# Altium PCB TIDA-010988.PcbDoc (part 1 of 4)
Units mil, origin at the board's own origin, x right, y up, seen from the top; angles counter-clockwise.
Board outline 3937.01 x 2559.06 mil, 4 copper layers (Top Layer, GND1, GND2, Bottom Layer), stack 61.6 mil thick; 270 components, 141 nets, 796 pads, 474 vias.
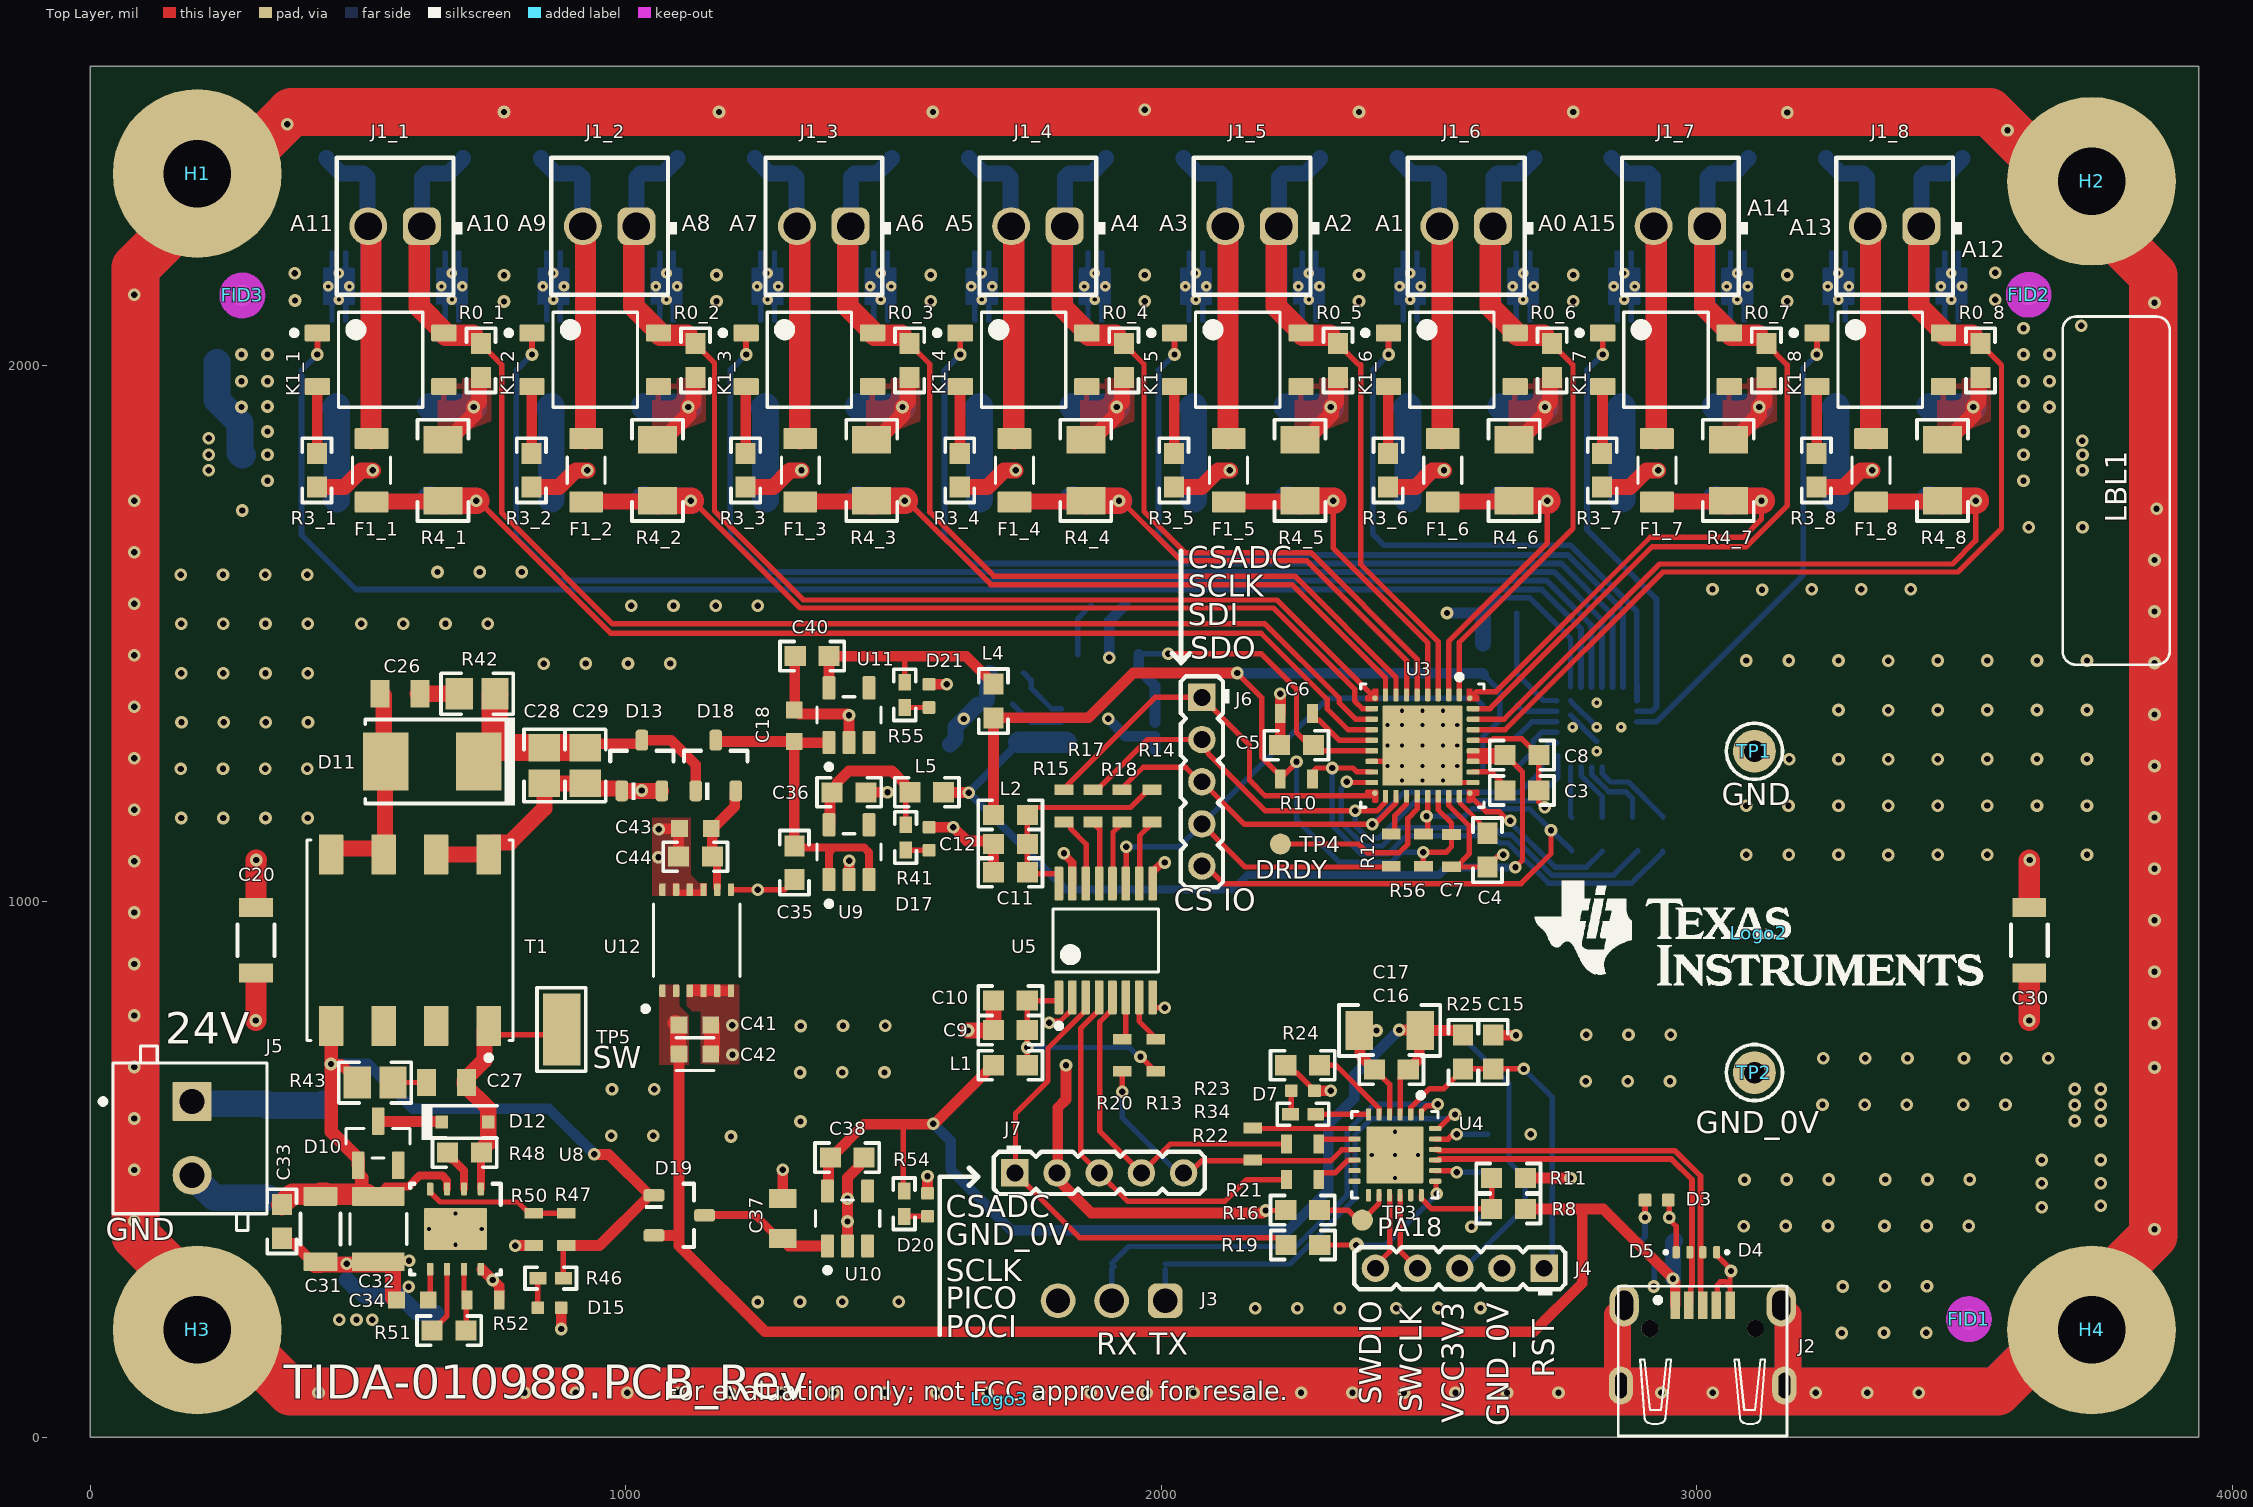
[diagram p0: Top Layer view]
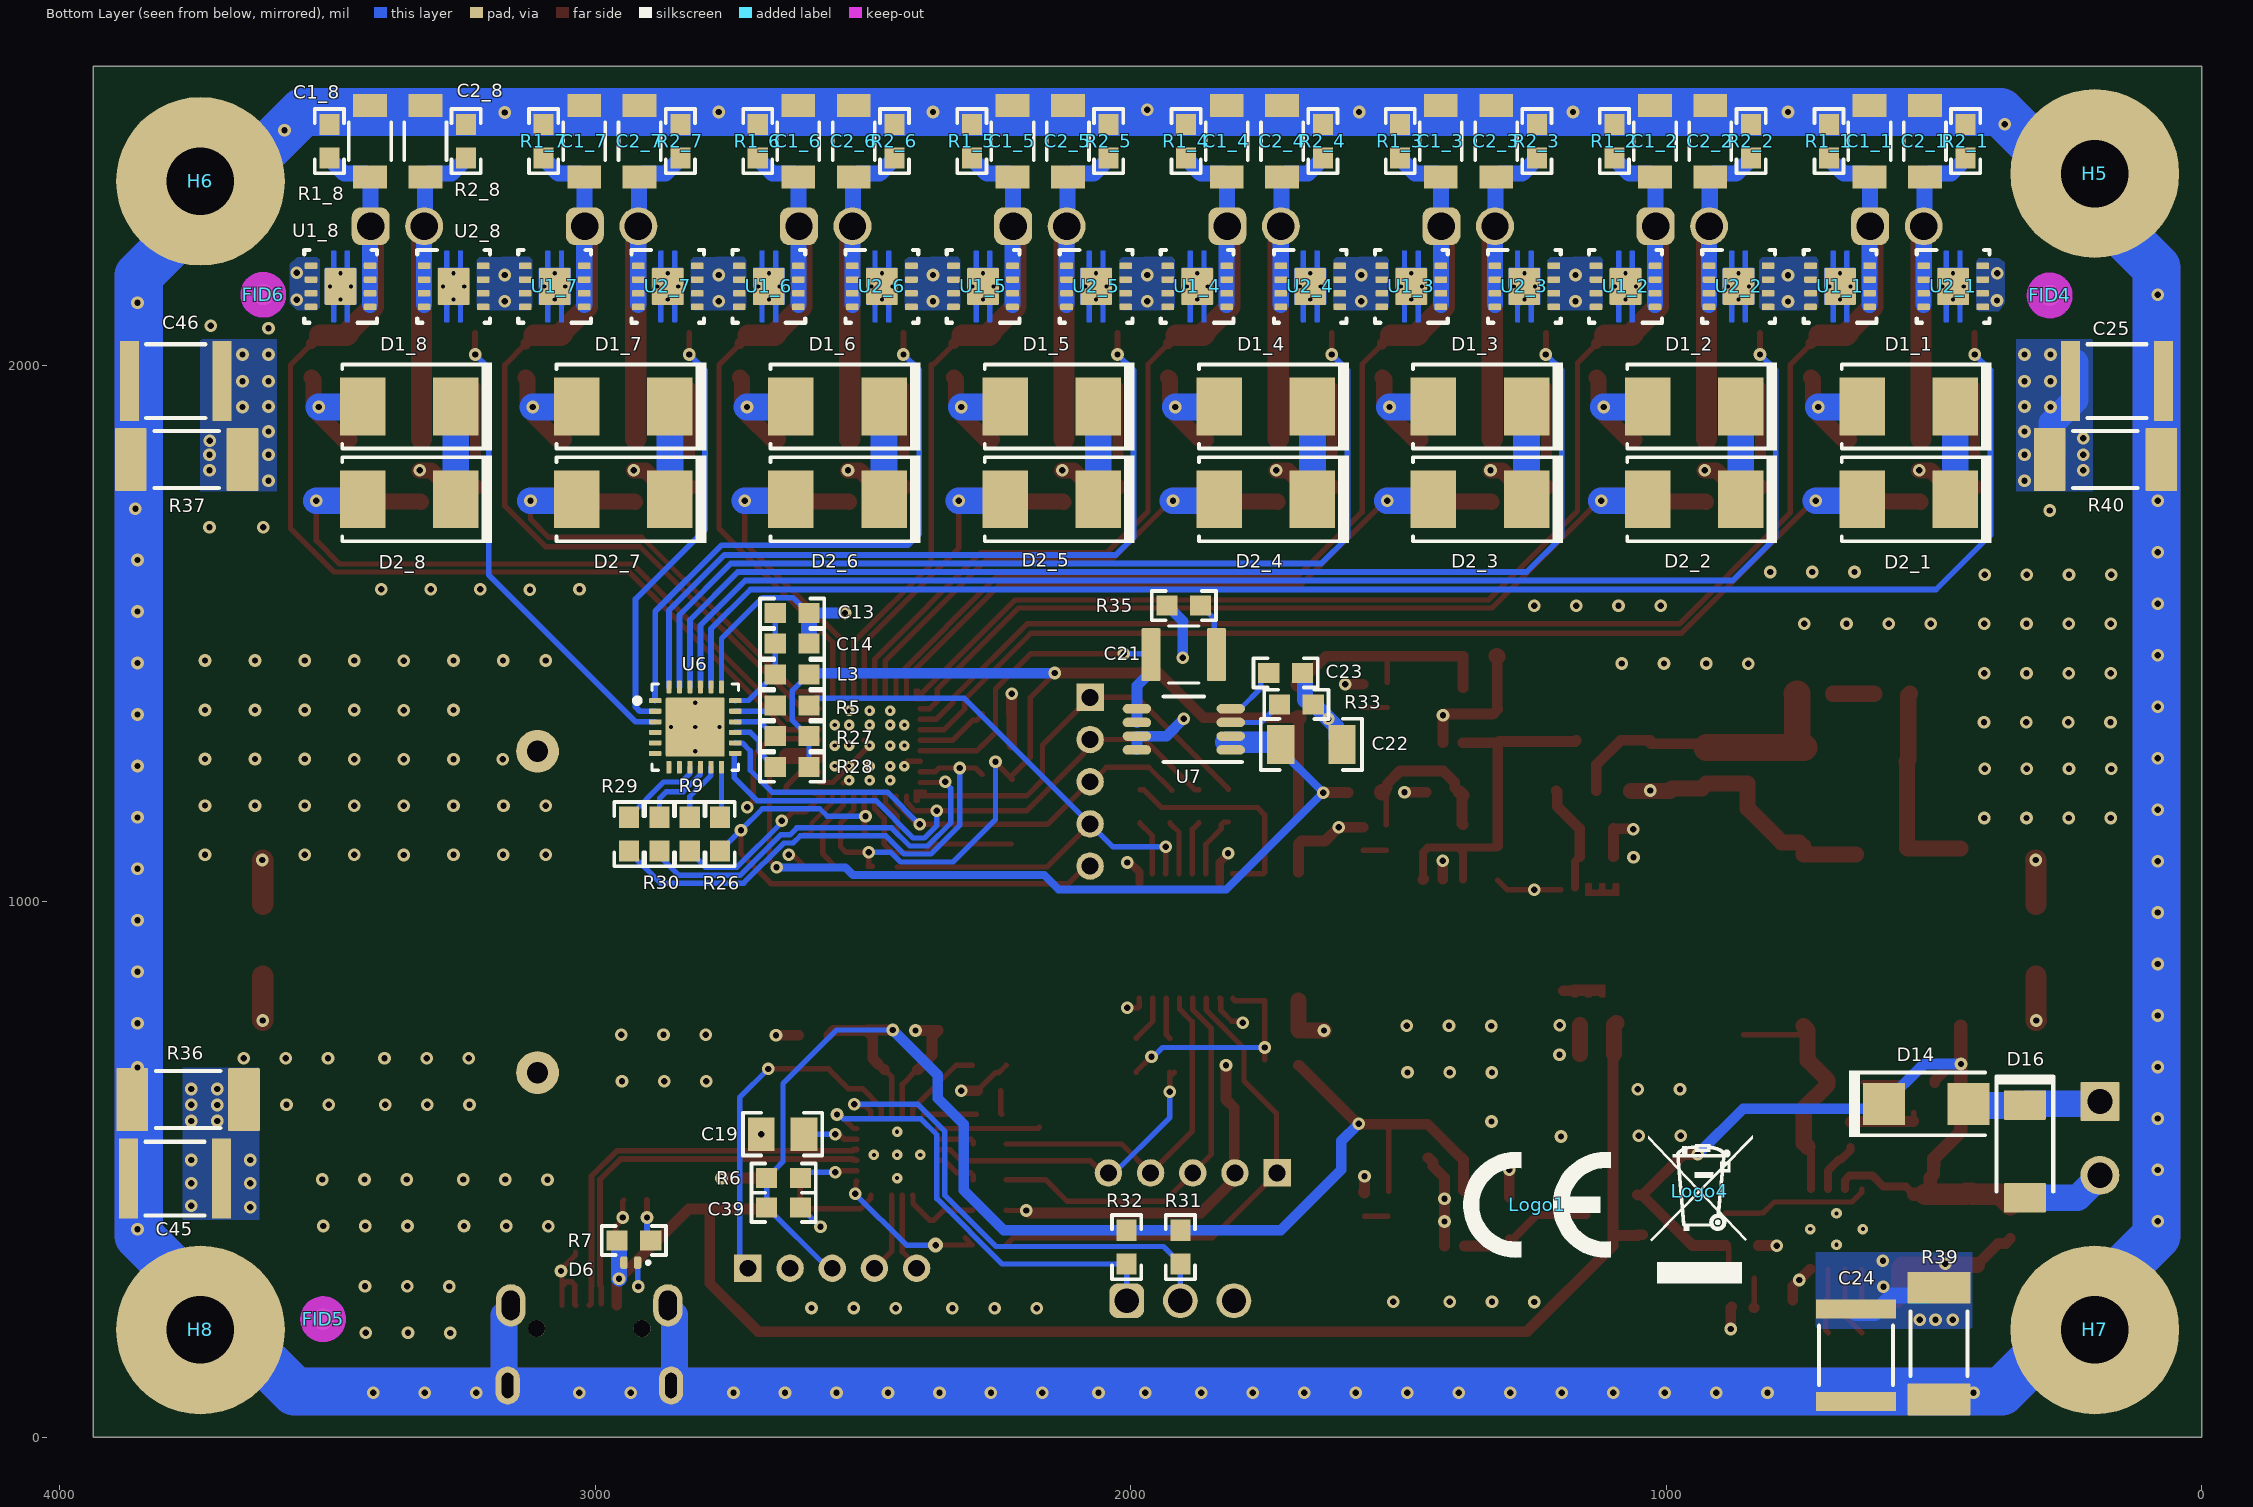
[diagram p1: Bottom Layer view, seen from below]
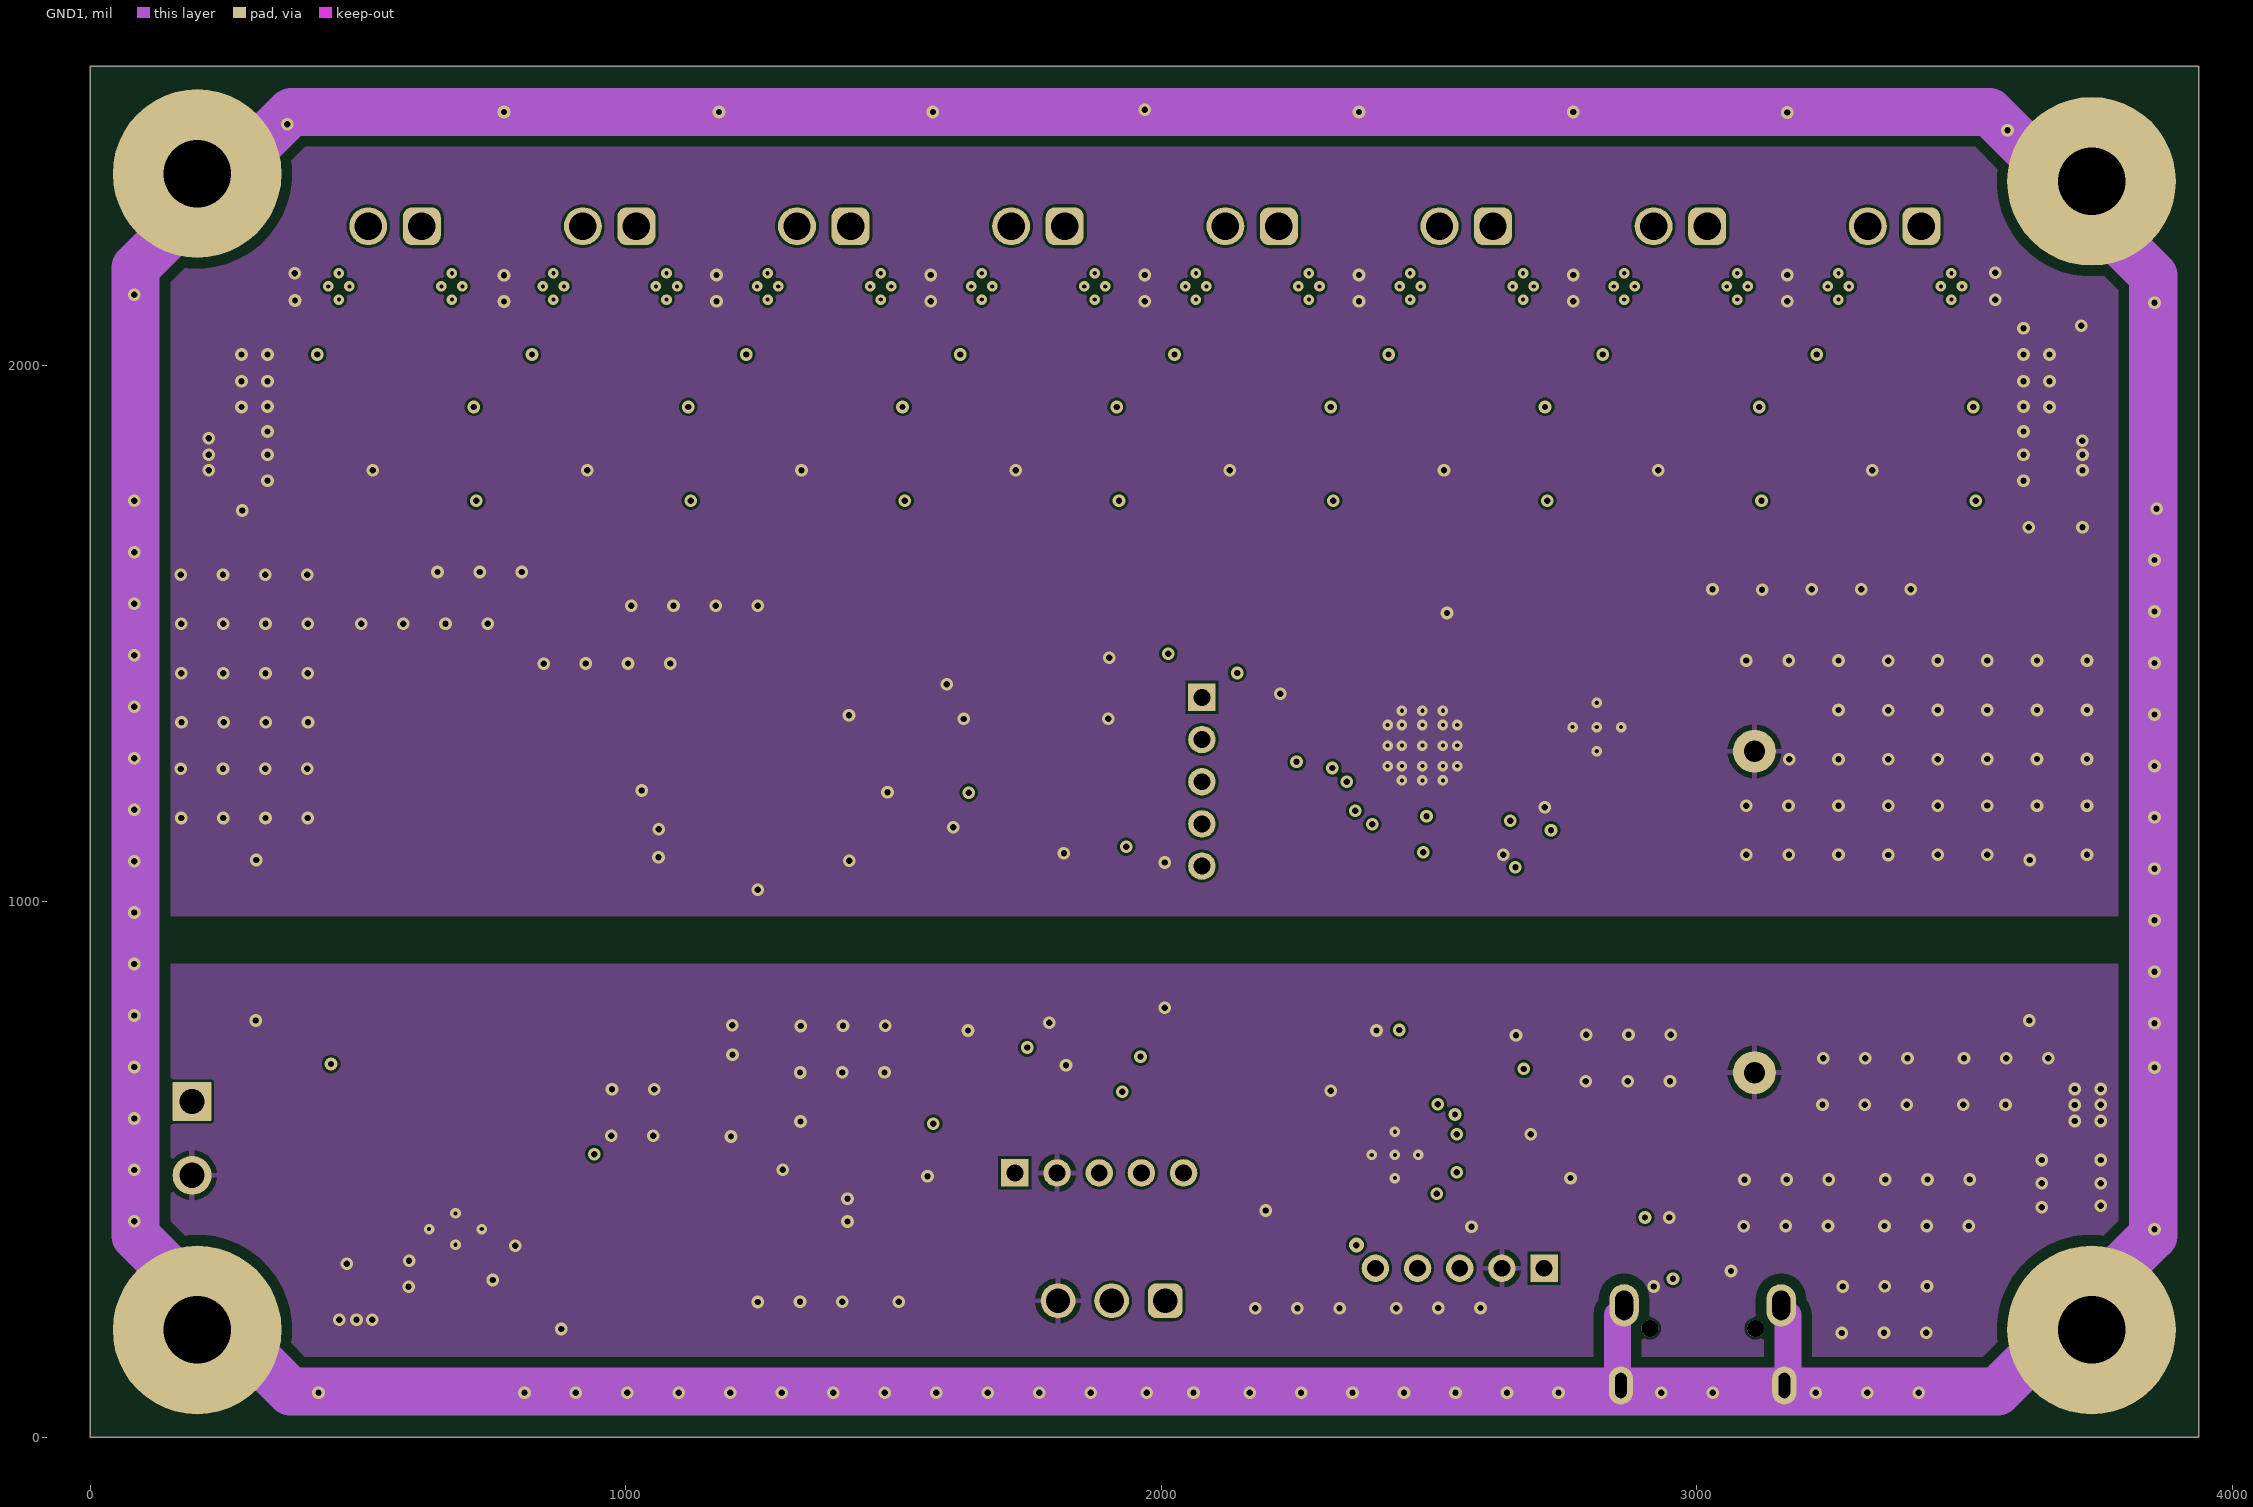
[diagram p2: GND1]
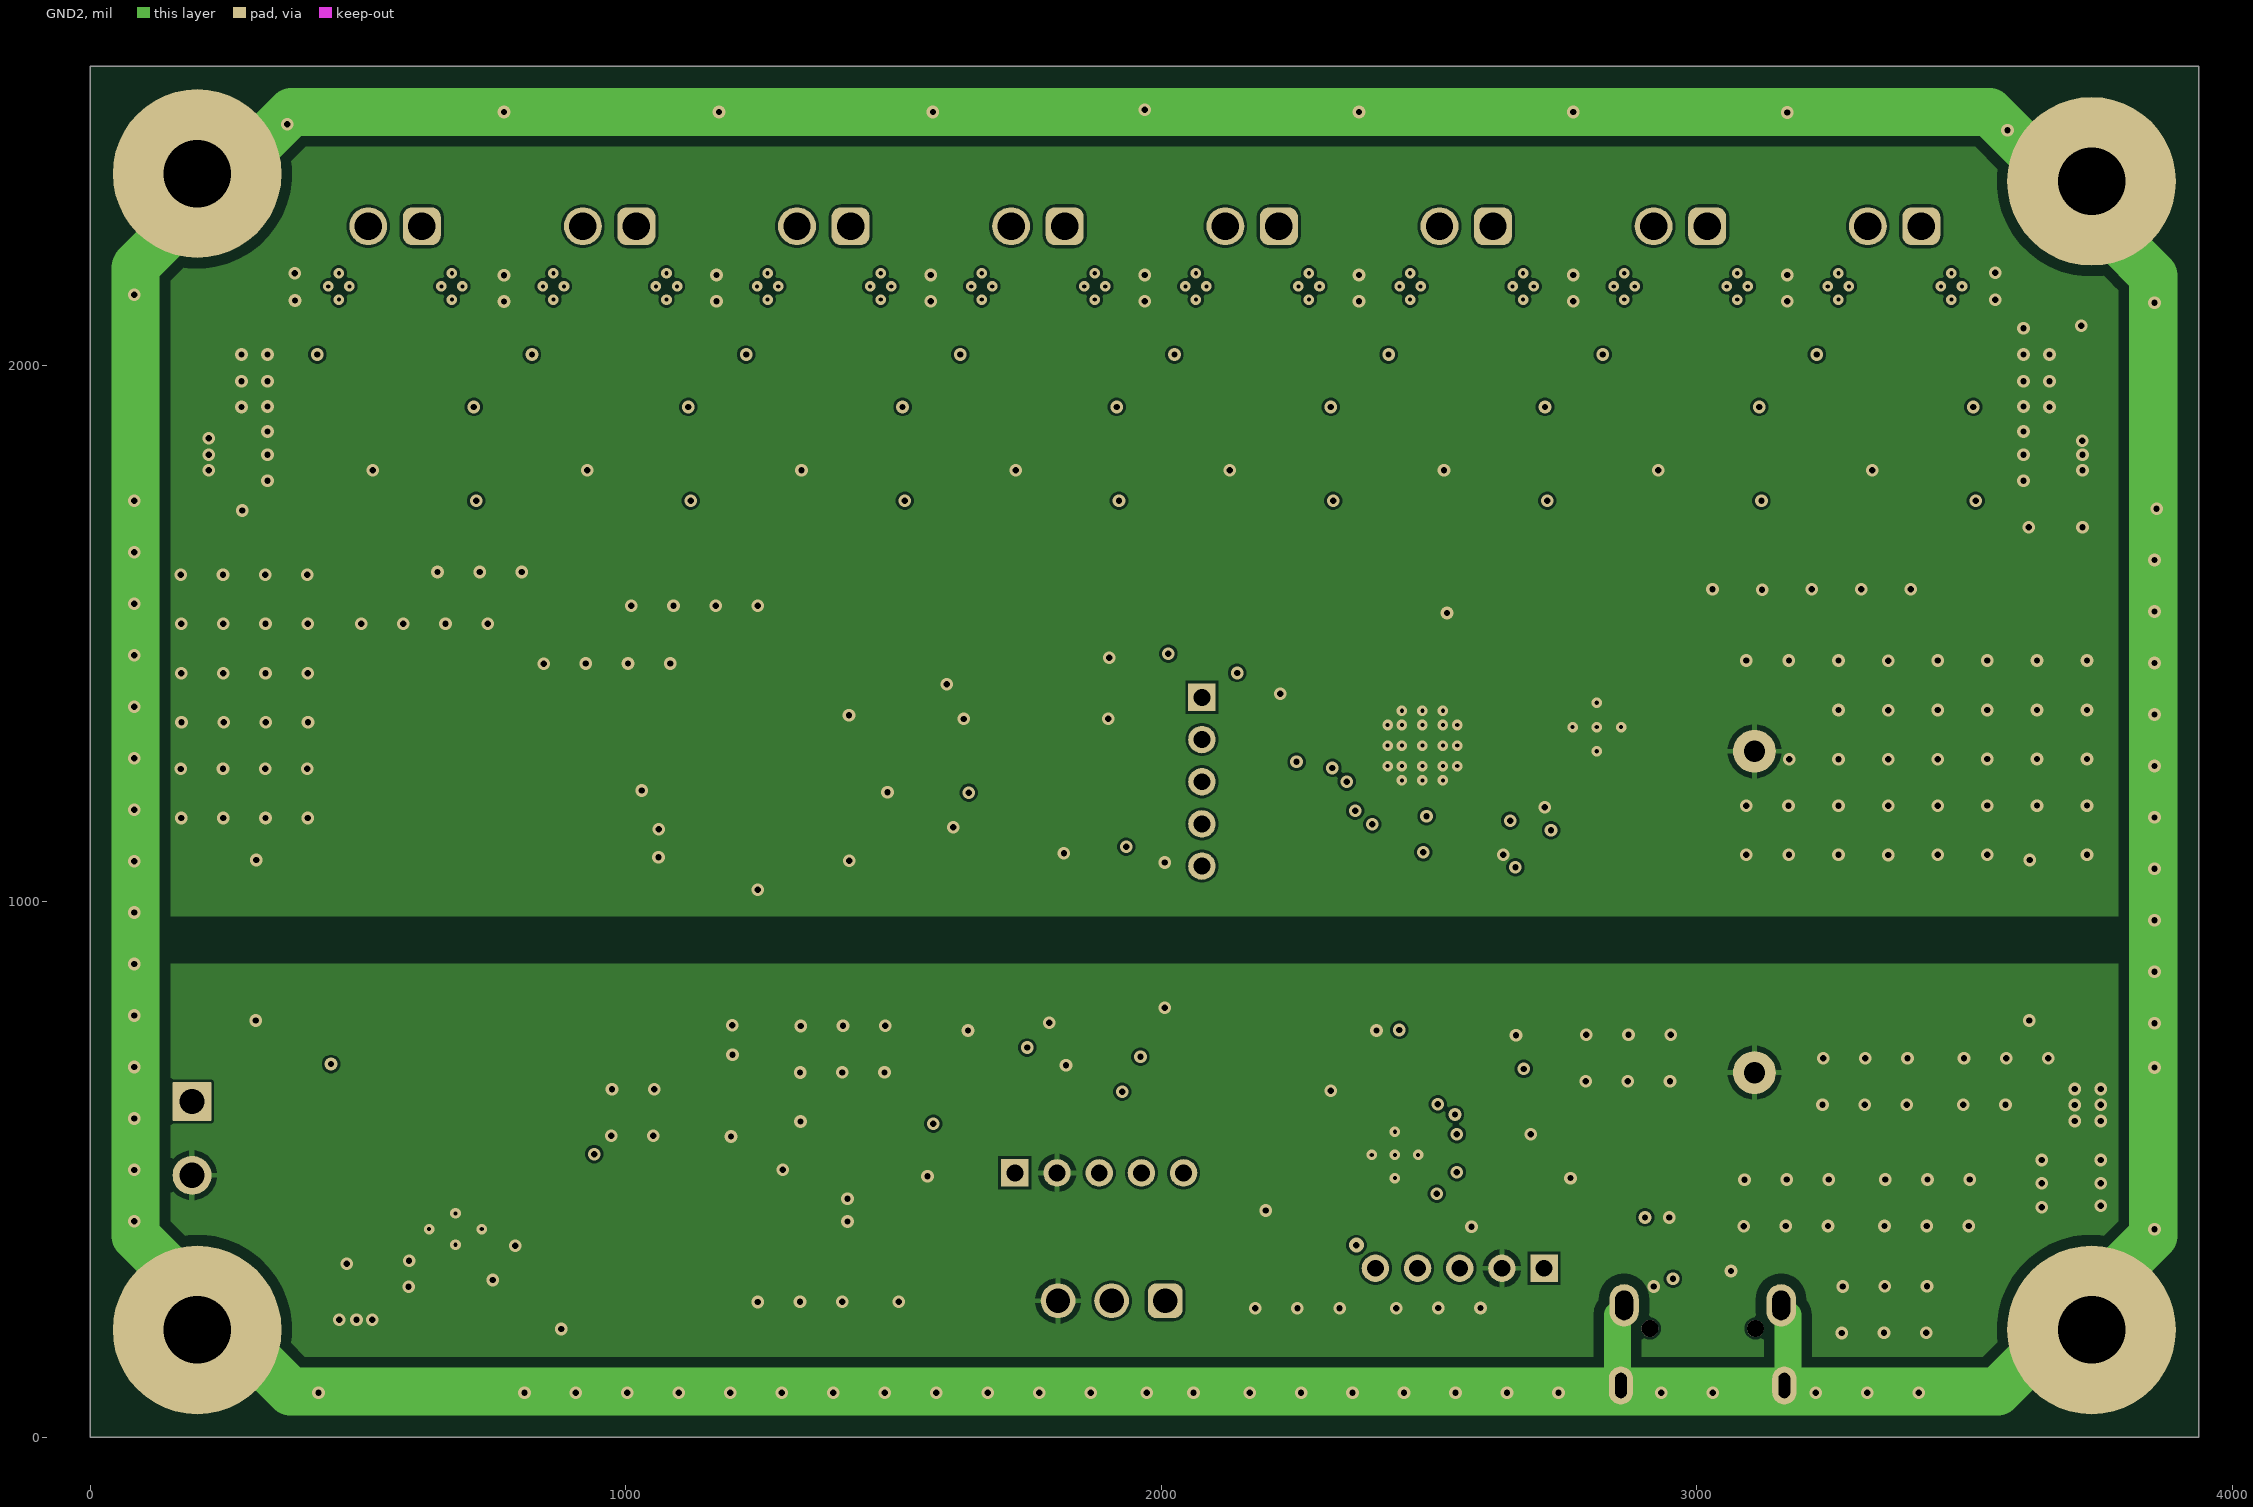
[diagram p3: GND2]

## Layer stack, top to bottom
Top Solder: solder mask 0.4, Solder Resist, Dk 3.5
Top Layer: signal copper 1.4
Dielectric 1: prepreg 9, PP-006, Dk 4.1
GND1: signal copper 1.4
Dielectric1: core 38, FR-4 High Tg, Dk 4.8
GND2: signal copper 1.4
Dielectric 2: prepreg 9, PP-006, Dk 4.1
Bottom Layer: signal copper 1.4
Bottom Solder: solder mask 0.4, Solder Resist, Dk 3.5

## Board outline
0,0 0,2559.06 3937.01,2559.06 3937.01,0

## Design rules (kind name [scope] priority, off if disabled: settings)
AcuteAngle [All] p1: minimum=4.50000000000000E+0001 checktracksonly=FALSE
AssemblyTestPointUsage [All] p1: valid=2
BoardOutlineClearance BoardOutlineClearance_MountingHoles [OnCopper and InComponentClass('Mounting Holes')] p1: gap=39.37 ignorepadtopadclearanceinfootprint=FALSE
BoardOutlineClearance BoardOutlineClearance_Poly [OnCopper and IsPoly] p2: gap=25 ignorepadtopadclearanceinfootprint=FALSE
BoardOutlineClearance [OnCopper and Not InComponentClass('Logo') and not InComponentClass('FiducialMark') and not InRegion(1000,500,4000,800) and not InPoly] p3: gap=40 ignorepadtopadclearanceinfootprint=FALSE
Clearance Clearance_EGND [InNet('E_GND')] p1: gap=20 ignorepadtopadclearanceinfootprint=TRUE
Clearance Clearance_Keepouts [((IsTrack Or IsArc) And Not InPoly) And IsFree and IsKeepOut vs ((IsTrack Or IsArc) And Not InPoly) And IsFree and IsKeepOut] p2: gap=0 ignorepadtopadclearanceinfootprint=FALSE
Clearance Clearance_Poly [InPolygon] p3: gap=5 ignorepadtopadclearanceinfootprint=TRUE
Clearance Clearance_FiducialMark [IsKeepOut and InComponentClass('FiducialMark') vs IsPad and InComponentClass('FiducialMark')] p4: gap=0 ignorepadtopadclearanceinfootprint=FALSE
Clearance [All] p5: gap=5 ignorepadtopadclearanceinfootprint=TRUE
ComponentClearance ComponentClearance_L3R29 [InComponent('R29') or InComponent('L3')] p1: gap=0 collisioncheckmode=3 verticalgap=0 showdistances=FALSE
ComponentClearance ComponentClearance_J2J3 [InComponent('J2') or InComponent('J3')] p2: gap=0 collisioncheckmode=3 verticalgap=0 showdistances=FALSE
ComponentClearance ComponentClearance_J4J5 [InComponent('J4') or InComponent('J5')] p3: gap=0 collisioncheckmode=3 verticalgap=0 showdistances=FALSE
ComponentClearance ComponentClearance_J11_J12 [InComponent('J11*') or InComponent('J12*')] p4: gap=0 collisioncheckmode=3 verticalgap=0 showdistances=FALSE
ComponentClearance ComponentClearance_MountingHoles_FiducialMarks [InComponentClass('Mounting Holes') vs InComponentClass('FiducialMark')] p5: gap=50 collisioncheckmode=3 verticalgap=10 showdistances=FALSE
ComponentClearance ComponentClearance_Shunt [InComponentClass('Header') vs InComponentClass('Shunt')] p6: gap=0 collisioncheckmode=3 verticalgap=0 showdistances=FALSE
ComponentClearance ComponentClearance_Logo [InComponentClass('Logo')] p7: gap=30 collisioncheckmode=3 verticalgap=10 showdistances=FALSE
ComponentClearance ComponentClearance_ScrewToNut [(HasFootprint('NY PMS 440 0025 PH')) vs (HasFootprint('Keystone_1902C'))] p8: gap=5 collisioncheckmode=3 verticalgap=10 showdistances=FALSE
ComponentClearance ComponentClearance_MountingHoles [InComponentClass('Mounting Holes')] p9: gap=78.74 collisioncheckmode=3 verticalgap=100000 showdistances=FALSE
ComponentClearance ComponentClearance_SmallPassives [HasFootprint('0201*') or HasFootprint('0402*') or HasFootprint('0508') or HasFootprint('0603*') or HasFootprint('0612') or HasFootprint('0805*') or HasFootprint('0815*') or HasFootprint('0830*') or HasFootprint('1206*') or HasFootprint('1210*') or HasFootprint('1808*') or HasFootprint('1812*') or HasFootprint('1825*') or HasFootprint('2010*') or HasFootprint('2220*') or HasFootprint('2225*') or HasFootprint('2512*') or HasFootprint('2728*') or HasFootprint('3518*') or HasFootprint('DPY0002A') vs HasFootprint('0201*') or HasFootprint('0402*') or HasFootprint('0508') or HasFootprint('0603*') or HasFootprint('0612') or HasFootprint('0805*') or HasFootprint('0815*') or HasFootprint('0830*') or HasFootprint('1206*') or HasFootprint('1210*') or HasFootprint('1808*') or HasFootprint('1812*') or HasFootprint('1825*') or HasFootprint('2010*') or HasFootprint('2220*') or HasFootprint('2225*') or HasFootprint('2512*') or HasFootprint('2728*') or HasFootprint('3518*') or HasFootprint('DPY0002A')] p10: gap=10 collisioncheckmode=3 verticalgap=10 showdistances=FALSE
ComponentClearance ComponentClearance_THtoSMT [IsThruComponent vs IsSMTComponent] p11: gap=20 collisioncheckmode=3 verticalgap=30 showdistances=FALSE
ComponentClearance ComponentClearance_THtoTH [IsThruComponent vs IsThruComponent] p12: gap=20 collisioncheckmode=3 verticalgap=30 showdistances=FALSE
ComponentClearance [All] p13: gap=10 collisioncheckmode=3 verticalgap=10 showdistances=FALSE
DiffPairsRouting DiffPairsRouting_1 [InDifferentialPairClass('D90')] p1: maxlimit=5 minlimit=5 mostfreqgap=5 toplayer_minwidth=10.82 toplayer_maxwidth=10.82 toplayer_prefwidth=10.82 midlayer1_minwidth=4.64 midlayer1_maxwidth=4.64 midlayer1_prefwidth=4.64 midlayer2_minwidth=4.64 midlayer2_maxwidth=4.64 midlayer2_prefwidth=4.64 bottomlayer_minwidth=10.82 bottomlayer_maxwidth=10.82 bottomlayer_prefwidth=10.82 impedanceprofiledriven=TRUE maxuncoupledlength=500
DiffPairsRouting [All] p2: maxlimit=100 minlimit=10 mostfreqgap=10 toplayer_minwidth=15 toplayer_maxwidth=15 toplayer_prefwidth=15 midlayer1_minwidth=15 midlayer1_maxwidth=15 midlayer1_prefwidth=15 midlayer2_minwidth=15 midlayer2_maxwidth=15 midlayer2_prefwidth=15 bottomlayer_minwidth=15 bottomlayer_maxwidth=15 bottomlayer_prefwidth=15 maxuncoupledlength=1000
FabricationTestPointUsage TestPointUsage [All] p1: valid=2 allowmultiple=FALSE
FabricationTestpoint Testpoint [All] p1: side=3 testpointundercomponent=TRUE minsize=40 maxsize=100 preferedsize=60 minholesize=0 maxholesize=40 preferedholesize=32 testpointgrid=1 allowsidetop=TRUE allowsidebottom=TRUE usegrid=TRUE gridtolerance=0.01
FanoutControl Fanout_LCC [IsLCC] p1: bgadir=Out bgaviamode=Centered fanoutstyle=Auto fanoutdirection=Alternating viagrid=1 // Fanout_LCC (Default Rule)
FanoutControl Fanout_BGA [IsBGA] p2: bgadir=Out bgaviamode=Centered fanoutstyle=Auto fanoutdirection=Alternating viagrid=1 // Fanout_BGA (Default Rule)
FanoutControl Fanout_Default [All] p4: bgadir=Out bgaviamode=Centered fanoutstyle=Auto fanoutdirection=Alternating viagrid=1 // Fanout_Default (Default Rule)
FanoutControl Fanout_Small [(CompPinCount < 5)] p5: bgadir=Out bgaviamode=Centered fanoutstyle=Auto fanoutdirection=OutThenIn viagrid=1 // Fanout_Small (Default Rule)
HoleSize [All] p1: absolutevalues=TRUE maxlimit=251 minlimit=7.87 maxpercent=80.000 minpercent=20.000
MinimumAnnularRing MinimumAnnularRing_ThermalPadVias [IsVia and InAnyComponent] p1: minimumring=5.91
MinimumAnnularRing [All] p2: minimumring=5.91
MinimumSolderMaskSliver MinimumSolderMaskSliver_Logo [InComponentClass('Logo') vs InComponentClass('Logo')] p1: minsoldermaskwidth=0.7
MinimumSolderMaskSliver [All] p2: minsoldermaskwidth=3.94
PlaneClearance PlaneClearance_1 [InNet('E_GND')] p1: clearance=100
PlaneClearance [All] p2: clearance=20
PlaneConnect [All] p1: planeconnectstyle=Relief reliefexpansion=10 reliefentries=4 reliefconductorwidth=10 reliefairgap=10
PolygonConnect PolygonConnect_SMD [HasFootprint('0201*') or HasFootprint('*0402*') or HasFootprint('0508') or HasFootprint('0603*') or HasFootprint('0612') or HasFootprint('0805*') or HasFootprint('0815*') or HasFootprint('0830*') or HasFootprint('*1206*') or HasFootprint('*1210*') or HasFootprint('1808*') or HasFootprint('1812*') or HasFootprint('1825*') or HasFootprint('2010*') or HasFootprint('2220*') or HasFootprint('2225*') or HasFootprint('2512*') or HasFootprint('2728*') or HasFootprint('3518*') or HasFootprint('DPY0002A') or IsVia or HasFootprint('DBV*') or HasFootprint('WE-LQS*') or HasFootprint('SM_RADIAL_C') or HasFootprint('DRB*') or HasFootprint('691382010004') or HasFootprint('691382010002') or HasFootprint('*SOD128*') or HasFootprint('WE-SLM') or HasFootprint('WCAP*') or HasFootprint('RAQ0012B-MFG')or HasFootprint('FP-CHV2010-FX-3304ELF_2010-MFG')] p1: connectstyle=Direct reliefconductorwidth=10 reliefentries=4 polygonreliefangle="90 Angle" airgapwidth=10
PolygonConnect [All] p2: connectstyle=Relief reliefconductorwidth=10 reliefentries=4 polygonreliefangle="90 Angle" airgapwidth=10
RoomDefinition IN1 [InComponentClass('IN1')] p1: confinementstyle=ConfineIn formatcopy=TRUE lockcomponents=FALSE outline 362.31,2512.47 362.31,1643.16 779.44,1643.16 779.44,2512.47
RoomDefinition IN3 [InComponentClass('IN3')] p2: confinementstyle=ConfineIn formatcopy=TRUE lockcomponents=TRUE outline 1162.79,2512.47 1162.79,1643.16 1579.92,1643.16 1579.92,2512.47
RoomDefinition IN2 [InComponentClass('IN2')] p3: confinementstyle=ConfineIn formatcopy=TRUE lockcomponents=FALSE outline 762.93,2512.47 762.93,1643.16 1180.06,1643.16 1180.06,2512.47
RoomDefinition IN5 [InComponentClass('IN5')] p4: confinementstyle=ConfineIn formatcopy=TRUE lockcomponents=FALSE outline 1962.51,2512.47 1962.51,1643.16 2379.64,1643.16 2379.64,2512.47
RoomDefinition IN4 [InComponentClass('IN4')] p5: confinementstyle=ConfineIn formatcopy=TRUE lockcomponents=FALSE outline 1562.65,2512.47 1562.65,1643.16 1979.78,1643.16 1979.78,2512.47
RoomDefinition IN6 [InComponentClass('IN6')] p6: confinementstyle=ConfineIn formatcopy=TRUE lockcomponents=FALSE outline 2362.37,2512.47 2362.37,1643.16 2779.5,1643.16 2779.5,2512.47
RoomDefinition IN7 [InComponentClass('IN7')] p7: confinementstyle=ConfineIn formatcopy=TRUE lockcomponents=FALSE outline 2762.24,2512.47 2762.24,1643.16 3179.36,1643.16 3179.36,2512.47
RoomDefinition IN8 [InComponentClass('IN8')] p8: confinementstyle=ConfineIn formatcopy=TRUE lockcomponents=FALSE outline 3162.1,2512.47 3162.1,1643.16 3579.23,1643.16 3579.23,2512.47
RoutingVias [All] p1: holewidth=11.81 width=23.62 viastyle="Through Hole" minholewidth=5.91 minwidth=18 maxholewidth=40 maxwidth=65
RoutingVias ThermalPadVias [IsVia and InAnyComponent] p2: holewidth=5 width=19.68 viastyle="Through Hole" minholewidth=5 minwidth=19.68 maxholewidth=12.99 maxwidth=23.62
SilkToBoardRegionClearance [Not ((IsComment or IsDesignator) And (Hide <> 'False')) and not InRegion(1000,500,4000,800)] p1:
SilkToSilkClearance SilkToSilkClearance_Pb-FreeLogo [(HasFootprint('Pb-Free_Overlay_Medium') OR HasFootprint('Pb-Free_Overlay_Small')) vs (HasFootprint('Pb-Free_Overlay_Medium') OR HasFootprint('Pb-Free_Overlay_Small'))] p1: silktosilkclearance=0
SilkToSilkClearance [All] p2: silktosilkclearance=3.94
SilkToSolderMaskClearance SilkToComponentPadClearance [(IsPad or IsFill or IsRegion) and InAnycomponent] p1: minsilkscreentomaskgap=5 clearancetoexposedcopper=TRUE
SilkToSolderMaskClearance "Silk to Solder Mask Opening" [All] p2: minsilkscreentomaskgap=3.94 clearancetoexposedcopper=FALSE
SolderMaskExpansion [All] p1: expansion=1.97 istentingtop=FALSE
UnRoutedNet [All] p1: checkbadconnections=TRUE
Width [All] p1: maxlimit=100 minlimit=6 preferedwidth=10 checkconnectedcopper=TRUE
13 further rules are at their usual default settings.

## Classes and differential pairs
component class Header: J3 J4 J6 J7
component class IN6: C1_6 C2_6 D1_6 D2_6 F1_6 J1_6 K1_6 R0_6 R1_6 R2_6 R3_6 R4_6 U1_6 U2_6
component class IN5: C1_5 C2_5 D1_5 D2_5 F1_5 J1_5 K1_5 R0_5 R1_5 R2_5 R3_5 R4_5 U1_5 U2_5
component class IN2: C1_2 C2_2 D1_2 D2_2 F1_2 J1_2 K1_2 R0_2 R1_2 R2_2 R3_2 R4_2 U1_2 U2_2
component class IN1: C1_1 C2_1 D1_1 D2_1 F1_1 J1_1 K1_1 R0_1 R1_1 R2_1 R3_1 R4_1 U1_1 U2_1
differential pair class D90: USB_D
channel class TIDA-010988_Input: IN1 IN2 IN3 IN4 IN5 IN6 IN7 IN8
component class U_TIDA-010988_Power: C18 C24 C25 C26 C27 C28 C29 C31 C32 C33 C34 C35 C36 C37 C38 C40 C41 C42 C43 C44 C45 C46 D10 D11 D12 D13 D14 D15 D16 D17 D18 D19 D20 D21 J5 R36 R37 R39 R40 R41 R42 R43 R46 R47 R48 R50 R51 R52 R54 R55 T1 TP5 U8 U9 U10 U11 U12
component class IN8: C1_8 C2_8 D1_8 D2_8 F1_8 J1_8 K1_8 R0_8 R1_8 R2_8 R3_8 R4_8 U1_8 U2_8
component class IN7: C1_7 C2_7 D1_7 D2_7 F1_7 J1_7 K1_7 R0_7 R1_7 R2_7 R3_7 R4_7 U1_7 U2_7
component class IN4: C1_4 C2_4 D1_4 D2_4 F1_4 J1_4 K1_4 R0_4 R1_4 R2_4 R3_4 R4_4 U1_4 U2_4
component class IN3: C1_3 C2_3 D1_3 D2_3 F1_3 J1_3 K1_3 R0_3 R1_3 R2_3 R3_3 R4_3 U1_3 U2_3
component class U_TIDA-010988_ADC+MCU: C3 C4 C5 C6 C7 C8 C9 C10 C11 C12 C13 C14 C15 C16 C17 C19 C20 C21 C22 C23 C30 C39 D3 D4 D5 D6 D7 J2 J3 J4 J6 J7 L1 L2 L3 L4 L5 R5 R6 R7 R8 R9 R10 R11 R12 R13 R14 R15 R16 R17 R18 R19 R20 R21 R22 R23 R24 R25 R26 R27 R28 R29 R30 R31 R32 R33 R34 R35 R56 TP1 TP2 TP3 TP4 U3 U4 U5 U6 U7
component class "Mounting Holes": H1 H2 H3 H4
component class Logo: Logo2
component class U_TIDA-010988_Hardware: FID1 FID2 FID3 FID4 FID5 FID6 H1 H2 H3 H4 H5 H6 H7 H8 LBL1 Logo1 Logo2 Logo3 Logo4 ZZ1 ZZ2 ZZ3 ZZ4
component class FiducialMark: FID1 FID2 FID3 FID4 FID5 FID6
component class AssemblyNote: ZZ1 ZZ2 ZZ3 ZZ4
component class Label: LBL1
differential pair USB_D: +USB_D_P -USB_D_N

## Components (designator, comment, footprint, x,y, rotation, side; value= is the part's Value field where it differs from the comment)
C1_1 "C1206C223KDRACTU" 1206_190 620.59,2419.41 r90 bottom value=0.022uF (schematic designator C1)
C1_2 "C1206C223KDRACTU" 1206_190 1021.21,2419.41 r90 bottom value=0.022uF (schematic designator C1)
C1_3 "C1206C223KDRACTU" 1206_190 1421.07,2419.41 r90 bottom value=0.022uF (schematic designator C1)
C1_4 "C1206C223KDRACTU" 1206_190 1820.93,2419.41 r90 bottom value=0.022uF (schematic designator C1)
C1_5 "C1206C223KDRACTU" 1206_190 2220.8,2419.41 r90 bottom value=0.022uF (schematic designator C1)
C1_6 "C1206C223KDRACTU" 1206_190 2620.66,2419.41 r90 bottom value=0.022uF (schematic designator C1)
C1_7 "C1206C223KDRACTU" 1206_190 3020.52,2419.41 r90 bottom value=0.022uF (schematic designator C1)
C1_8 "C1206C223KDRACTU" 1206_190 3420.38,2419.41 r90 bottom value=0.022uF (schematic designator C1)
C2_1 "C1206C223KDRACTU" 1206_190 517.16,2419.41 r270 bottom value=0.022uF (schematic designator C2)
C2_2 "C1206C223KDRACTU" 1206_190 917.78,2419.41 r270 bottom value=0.022uF (schematic designator C2)
C2_3 "C1206C223KDRACTU" 1206_190 1317.64,2419.41 r270 bottom value=0.022uF (schematic designator C2)
C2_4 "C1206C223KDRACTU" 1206_190 1717.51,2419.41 r270 bottom value=0.022uF (schematic designator C2)
C2_5 "C1206C223KDRACTU" 1206_190 2117.37,2419.41 r270 bottom value=0.022uF (schematic designator C2)
C2_6 "C1206C223KDRACTU" 1206_190 2517.23,2419.41 r270 bottom value=0.022uF (schematic designator C2)
C2_7 "C1206C223KDRACTU" 1206_190 2917.09,2419.41 r270 bottom value=0.022uF (schematic designator C2)
C2_8 "C1206C223KDRACTU" 1206_190 3316.95,2419.41 r270 bottom value=0.022uF (schematic designator C2)
C3 "885012206076" 0603 2673.43,1207.13 r0 top value=1uF
C4 "885012206076" 0603 2609.12,1095.82 r270 top value=1uF
C5 "885012206076" 0603 2252.41,1291.67 r180 top value=1uF
C6 "885012206076" 0603S 2252.41,1350.91 r180 top value=1uF
C7 "885012206076" 0603S 2541.89,1094.99 r270 top value=1uF
C8 "885012206076" 0603 2673.49,1273.08 r0 top value=1uF
C9 "885012206071" 0603 1718.26,759.71 r180 top value=0.1uF
C10 "885012206071" 0603 1718.26,814.71 r180 top value=0.1uF
C11 "885012206071" 0603 1718.48,1054.5 r180 top value=0.1uF
C12 "885012206071" 0603 1718.48,1107.22 r180 top value=0.1uF
C13 "885012206071" 0603 2632.33,1538.44 r180 bottom value=0.1uF
C14 "885012206071" 0603 2632.33,1481.39 r180 bottom value=0.1uF
C15 "C0603H103J3GACTU" 0603 2619.89,718.78 r90 top value=0.01uF
C16 "885012206071" 0603 2429.63,685.94 r0 top value=0.1uF
C17 "885012208069" 1206 2426.47,758.98 r0 top value=10uF
C18 "885012206075" WCAP-CSGP_0603_L1.6W0.8H0.8_Reflow 1314.86,1328.04 r270 top
C19 "08053D474KAT2A" 0805_HV 2650.04,565.5 r180 bottom value=0.47uF
C20 "885342208024" WCAP-CSMH_1206_L3.2W1.6H1.6 309.72,927.55 r90 top
C21 "885012209074" FP-885012209074_1210-MFG 1900.9,1460.88 r0 bottom value=22µF
C22 "885012208069" 1206 1662.69,1293.28 r180 bottom value=10uF
C23 "885012206076" 0603 1710.87,1426.58 r180 bottom value=1uF
C24 "885342211010" WCAP-CSMH_1812_L4.5W3.2H2.5 645.9,152.76 r90 bottom
C25 "885342211010" WCAP-CSMH_1812_L4.5W3.2H2.5 158.35,1971.48 r180 bottom
C26 "885012007053" WCAP-CSGP_0805_L2W1.25H0.6_Reflow 578.32,1387.79 r0 top
C27 "885012007053" WCAP-CSGP_0805_L2W1.25H0.6_Reflow 665.5,661.94 r180 top
C28 "GRM21BR61A476ME15L" 0805 848.15,1253.81 r270 top value=47uF
C29 "GRM21BR61A476ME15L" 0805 924.62,1253.81 r270 top value=47uF
C30 "885342208024" WCAP-CSMH_1206_L3.2W1.6H1.6 3620.87,927.55 r90 top
C31 "885012208094" FP-885012208094_1206-MFG 430.09,388.27 r90 top
C32 "885012209048" FP-885012209048_1210-MFG 538.17,388.27 r90 top value=4.7µF
C33 "885012206095" 0603 358,402.57 r270 top value=0.1uF
C34 "885012206093" WCAP-CSGP_0603_L1.6W0.8H0.8_Reflow 601.95,255.9 r0 top
C35 "885012206052" 0603 1314.86,1072.25 r270 top value=1uF
C36 "885012206052" 0603 1417.01,1203.81 r0 top value=1uF
C37 "885012207130" WCAP-CSGP_0805_L2W1.25H1.25 1293.38,408 r270 top
C38 "885012206052" 0603 1413.7,521.67 r0 top value=1uF
C39 "885012206071" 0603 2648.35,428.8 r180 bottom value=0.1uF
C40 "885012206052" 0603 1348.11,1457.99 r180 top value=1uF
C41 "885012206066" WCAP-CSGP_0603_L1.6W0.8H0.8_Reflow 1129.3,769.55 r180 top
C42 "885012106031" FP-885012106031_0603-MFG 1129.3,715.09 r180 top value=10µF
C43 "885012206066" WCAP-CSGP_0603_L1.6W0.8H0.8_Reflow 1130.26,1136.23 r0 top
C44 "CL10A226MO7JZNC" 0603 1130.26,1083.52 r180 top value=22uF
C45 "885342211010" WCAP-CSMH_1812_L4.5W3.2H2.5 3784.71,482.36 r180 bottom
C46 "885342211010" WCAP-CSMH_1812_L4.5W3.2H2.5 3782.95,1971.48 r0 bottom
D1_1 "1SMB5926BT3G" SMB 547.43,1924.23 r0 bottom value=11V (schematic designator D1)
D1_2 "1SMB5926BT3G" SMB 948.05,1924.23 r0 bottom value=11V (schematic designator D1)
D1_3 "1SMB5926BT3G" SMB 1347.91,1924.22 r0 bottom value=11V (schematic designator D1)
D1_4 "1SMB5926BT3G" SMB 1747.77,1924.23 r0 bottom value=11V (schematic designator D1)
D1_5 "1SMB5926BT3G" SMB 2147.63,1924.22 r0 bottom value=11V (schematic designator D1)
D1_6 "1SMB5926BT3G" SMB 2547.49,1924.22 r0 bottom value=11V (schematic designator D1)
D1_7 "1SMB5926BT3G" SMB 2947.36,1924.22 r0 bottom value=11V (schematic designator D1)
D1_8 "1SMB5926BT3G" SMB 3347.21,1924.22 r0 bottom value=11V (schematic designator D1)
D2_1 "1SMB5926BT3G" SMB 547.44,1751.06 r0 bottom value=11V (schematic designator D2)
D2_2 "1SMB5926BT3G" SMB 948.05,1751.05 r0 bottom value=11V (schematic designator D2)
D2_3 "1SMB5926BT3G" SMB 1347.91,1751.05 r0 bottom value=11V (schematic designator D2)
D2_4 "1SMB5926BT3G" SMB 1747.77,1751.05 r0 bottom value=11V (schematic designator D2)
D2_5 "1SMB5926BT3G" SMB 2147.63,1751.05 r0 bottom value=11V (schematic designator D2)
D2_6 "1SMB5926BT3G" SMB 2547.49,1751.05 r0 bottom value=11V (schematic designator D2)
D2_7 "1SMB5926BT3G" SMB 2947.36,1751.05 r0 bottom value=11V (schematic designator D2)
D2_8 "1SMB5926BT3G" SMB 3347.21,1751.05 r0 bottom value=11V (schematic designator D2)
D3 "150040GS73240" WL-SMCC_0402_Green 2924.99,442.42 r180 top value=Green
D4 "ESD401DPYR" DPY0002A#1 3024.03,344.98 r180 top
D5 "ESD401DPYR" DPY0002A#1 2974.35,344.98 r0 top
D6 "ESD401DPYR" DPY0002A#2 2933.53,325.55 r0 bottom
D7 "150040GS73240" WL-SMCC_0402_Green 2264.43,646.62 r180 top value=Green
D10 "BZX84C27VDBZRQ1" DBZ0003A-MFG 537.79,548.55 r90 top
D11 "VS-20BQ030HM3/5BT" SMB 638.69,1261.33 r180 top value=30V
D12 "CMDD4448" SOD-323 700.11,588.14 r0 top value=75V
D13 "BZX84B8V2LT1G" SOT-23 1030.21,1253.81 r90 top value=8.2V
D14 "B340A-13-F" SMA 514.71,622.04 r180 bottom value=40V
D15 "150040GS73240" WL-SMCC_0402_Green 857.77,241.34 r180 top value=Green
D16 "RBS1LAM40ATR" FP-RBS1LAM40ATR_SOD128-MFG 330.54,533.25 r270 bottom
D17 "150040GS73240" WL-SMCC_0402_Green 1566.44,1116.94 r270 top value=Green
D18 "SDM40E20LC-7" SOT-23 1168.16,1253.81 r90 top value=20V
D19 "SDM40E20LC-7" SOT-23 1100.07,413.86 r0 top value=20V
D20 "150040GS73240" WL-SMCC_0402_Green 1563.67,433.59 r270 top value=Green
D21 "150040GS73240" WL-SMCC_0402_Green 1566.44,1383.7 r270 top value=Green
F1_1 "nanoASMDCH020F-2" FP-nanoASMDCH020F-2_1206-MFG 525.61,1805.02 r270 top (schematic designator F1)
F1_2 "nanoASMDCH020F-2" FP-nanoASMDCH020F-2_1206-MFG 926.23,1805.02 r270 top (schematic designator F1)
F1_3 "nanoASMDCH020F-2" FP-nanoASMDCH020F-2_1206-MFG 1326.09,1805.02 r270 top (schematic designator F1)
F1_4 "nanoASMDCH020F-2" FP-nanoASMDCH020F-2_1206-MFG 1725.95,1805.02 r270 top (schematic designator F1)
F1_5 "nanoASMDCH020F-2" FP-nanoASMDCH020F-2_1206-MFG 2125.81,1805.02 r270 top (schematic designator F1)
F1_6 "nanoASMDCH020F-2" FP-nanoASMDCH020F-2_1206-MFG 2525.67,1805.02 r270 top (schematic designator F1)
F1_7 "nanoASMDCH020F-2" FP-nanoASMDCH020F-2_1206-MFG 2925.53,1805.02 r270 top (schematic designator F1)
F1_8 "nanoASMDCH020F-2" FP-nanoASMDCH020F-2_1206-MFG 3325.4,1805.02 r270 top (schematic designator F1)
FID1 "Fiducial" Fiducial10-20 3507.94,220 r0 top
FID2 "Fiducial" Fiducial10-20 3619.74,2132.75 r0 top
FID3 "Fiducial" Fiducial10-20 284.33,2131.43 r0 top
FID4 "Fiducial" Fiducial10-20 284.33,2131.43 r180 bottom
FID5 "Fiducial" Fiducial10-20 3507.94,220 r180 bottom
FID6 "Fiducial" Fiducial10-20 3619.74,2132.75 r180 bottom
H1 "NY PMS 440 0025 PH" "NY PMS 440 0025 PH" 200,2359.06 r0 top locked
H2 "NY PMS 440 0025 PH" "NY PMS 440 0025 PH" 3737.01,2344.49 r0 top
H3 "NY PMS 440 0025 PH" "NY PMS 440 0025 PH" 200,200 r0 top
H4 "NY PMS 440 0025 PH" "NY PMS 440 0025 PH" 3737.01,200 r0 top locked
H5 "1902C" Keystone_1902C 200,2359.06 r180 bottom locked
H6 "1902C" Keystone_1902C 3737.01,2344.49 r180 bottom
H7 "1902C" Keystone_1902C 200,200 r180 bottom locked
H8 "1902C" Keystone_1902C 3737.01,200 r180 bottom locked
J1_1 "691210910002" Wurth_691210910002 569.41,2260.7 r180 top (schematic designator J1)
J1_2 "691210910002" Wurth_691210910002 970.03,2260.7 r180 top (schematic designator J1)
J1_3 "691210910002" Wurth_691210910002 1369.89,2260.7 r180 top (schematic designator J1)
J1_4 "691210910002" Wurth_691210910002 1769.75,2260.7 r180 top (schematic designator J1)
J1_5 "691210910002" Wurth_691210910002 2169.61,2260.7 r180 top (schematic designator J1)
J1_6 "691210910002" Wurth_691210910002 2569.48,2260.7 r180 top (schematic designator J1)
J1_7 "691210910002" Wurth_691210910002 2969.34,2260.7 r180 top (schematic designator J1)
J1_8 "691210910002" Wurth_691210910002 3369.2,2260.7 r180 top (schematic designator J1)
J2 "629105150521" FP-629105150521_CONN_USB_8MM0_6MM6-MFG 3010.8,245.88 r0 top locked
J3 "61300311121" WURTH_61300311121 1907.36,254.42 r180 top
J4 "M22-2510505" Harwin_M22-2510505 2557.32,315.11 r180 top
J5 "691103110002" FP-691103110002_CONN_TERM_POS2-MFG 186.54,557.54 r270 top
J6 "M22-2510505" Harwin_M22-2510505 2075.9,1223.53 r270 top
J7 "M22-2510505" Harwin_M22-2510505 1884.18,493.2 r0 top
K1_1 "AQY232G3HS" FP-AQY232G3HS_SOP4-MFG 542.51,2011.39 r0 top (schematic designator K1)
K1_2 "AQY232G3HS" FP-AQY232G3HS_SOP4-MFG 943.13,2011.39 r0 top (schematic designator K1)
K1_3 "AQY232G3HS" FP-AQY232G3HS_SOP4-MFG 1342.99,2011.39 r0 top (schematic designator K1)
K1_4 "AQY232G3HS" FP-AQY232G3HS_SOP4-MFG 1742.85,2011.39 r0 top (schematic designator K1)
K1_5 "AQY232G3HS" FP-AQY232G3HS_SOP4-MFG 2142.72,2011.39 r0 top (schematic designator K1)
K1_6 "AQY232G3HS" FP-AQY232G3HS_SOP4-MFG 2542.58,2011.39 r0 top (schematic designator K1)
K1_7 "AQY232G3HS" FP-AQY232G3HS_SOP4-MFG 2942.44,2011.39 r0 top (schematic designator K1)
K1_8 "AQY232G3HS" FP-AQY232G3HS_SOP4-MFG 3342.3,2011.39 r0 top (schematic designator K1)
L1 "782633601" 0603 1718.26,694.17 r0 top value="600 ohm"
L2 "782633601" 0603 1718.48,1161.6 r180 top value="600 ohm"
L3 "782633601" 0603 2632.33,1423.79 r0 bottom value="600 ohm"
L4 "782633601" 0603 1686.73,1374.24 r90 top value="600 ohm"
L5 "782633601" 0603 1562.19,1203.87 r180 top value="600 ohm"
LBL1 "THT-14-423-10" Label_650x200 3782.95,1767.15 r90 top
Logo1 "CE Mark" CE_Mark_5mm 1241.25,433.53 r180 bottom
Logo2 "Texas Instruments" TI_Stacked_Overlay_Small 3115.94,940.73 r0 top
Logo3 "FCC disclaimer" FCC_disclaimer 1697.83,70.39 r0 top
Logo4 "WEEE logo" WEEE_Minimum 937.99,459.18 r180 bottom
R0_1 "CRCW06030000Z0EA" 0603 729.87,2010.1 r90 top value=0 (schematic designator R0)
R0_2 "CRCW06030000Z0EA" 0603 1130.49,2010.1 r90 top value=0 (schematic designator R0)
R0_3 "CRCW06030000Z0EA" 0603 1530.35,2010.1 r90 top value=0 (schematic designator R0)
R0_4 "CRCW06030000Z0EA" 0603 1930.21,2010.1 r90 top value=0 (schematic designator R0)
R0_5 "CRCW06030000Z0EA" 0603 2330.07,2010.1 r90 top value=0 (schematic designator R0)
R0_6 "CRCW06030000Z0EA" 0603 2729.93,2010.1 r90 top value=0 (schematic designator R0)
R0_7 "CRCW06030000Z0EA" 0603 3129.79,2010.1 r90 top value=0 (schematic designator R0)
R0_8 "CRCW06030000Z0EA" 0603 3529.66,2010.1 r90 top value=0 (schematic designator R0)
R1_1 "CRCW060310M0DHEAP" 0603 696.37,2419.41 r270 bottom value=10Meg (schematic designator R1)
R1_2 "CRCW060310M0DHEAP" 0603 1096.98,2419.41 r270 bottom value=10Meg (schematic designator R1)
R1_3 "CRCW060310M0DHEAP" 0603 1496.85,2419.41 r270 bottom value=10Meg (schematic designator R1)
R1_4 "CRCW060310M0DHEAP" 0603 1896.71,2419.41 r270 bottom value=10Meg (schematic designator R1)
R1_5 "CRCW060310M0DHEAP" 0603 2296.57,2419.41 r270 bottom value=10Meg (schematic designator R1)
R1_6 "CRCW060310M0DHEAP" 0603 2696.43,2419.41 r270 bottom value=10Meg (schematic designator R1)
R1_7 "CRCW060310M0DHEAP" 0603 3096.29,2419.41 r270 bottom value=10Meg (schematic designator R1)
R1_8 "CRCW060310M0DHEAP" 0603 3496.15,2419.41 r270 bottom value=10Meg (schematic designator R1)
R2_1 "CRCW060310M0DHEAP" 0603 441.07,2419.41 r90 bottom value=10Meg (schematic designator R2)
R2_2 "CRCW060310M0DHEAP" 0603 841.68,2419.41 r90 bottom value=10Meg (schematic designator R2)
R2_3 "CRCW060310M0DHEAP" 0603 1241.54,2419.41 r90 bottom value=10Meg (schematic designator R2)
R2_4 "CRCW060310M0DHEAP" 0603 1641.41,2419.41 r90 bottom value=10Meg (schematic designator R2)
R2_5 "CRCW060310M0DHEAP" 0603 2041.27,2419.41 r90 bottom value=10Meg (schematic designator R2)
R2_6 "CRCW060310M0DHEAP" 0603 2441.13,2419.41 r90 bottom value=10Meg (schematic designator R2)
R2_7 "CRCW060310M0DHEAP" 0603 2840.99,2419.41 r90 bottom value=10Meg (schematic designator R2)
R2_8 "CRCW060310M0DHEAP" 0603 3240.85,2419.41 r90 bottom value=10Meg (schematic designator R2)
R3_1 "RT0603BRD07340RL" 0603 423.44,1805.02 r90 top value=340 (schematic designator R3)
R3_2 "RT0603BRD07340RL" 0603 824.06,1805.02 r90 top value=340 (schematic designator R3)
R3_3 "RT0603BRD07340RL" 0603 1223.92,1805.02 r90 top value=340 (schematic designator R3)
R3_4 "RT0603BRD07340RL" 0603 1623.79,1805.02 r90 top value=340 (schematic designator R3)
R3_5 "RT0603BRD07340RL" 0603 2023.65,1805.02 r90 top value=340 (schematic designator R3)
R3_6 "RT0603BRD07340RL" 0603 2423.51,1805.02 r90 top value=340 (schematic designator R3)
R3_7 "RT0603BRD07340RL" 0603 2823.37,1805.02 r90 top value=340 (schematic designator R3)
R3_8 "RT0603BRD07340RL" 0603 3223.23,1805.02 r90 top value=340 (schematic designator R3)
R4_1 "TNPW1206249RBEEA" 1206 658.8,1805.02 r90 top value=249 (schematic designator R4)
R4_2 "TNPW1206249RBEEA" 1206 1059.42,1805.02 r90 top value=249 (schematic designator R4)
R4_3 "TNPW1206249RBEEA" 1206 1459.28,1805.02 r90 top value=249 (schematic designator R4)
R4_4 "TNPW1206249RBEEA" 1206 1859.14,1805.02 r90 top value=249 (schematic designator R4)
R4_5 "TNPW1206249RBEEA" 1206 2259,1805.02 r90 top value=249 (schematic designator R4)
R4_6 "TNPW1206249RBEEA" 1206 2658.86,1805.02 r90 top value=249 (schematic designator R4)
R4_7 "TNPW1206249RBEEA" 1206 3058.72,1805.02 r90 top value=249 (schematic designator R4)
R4_8 "TNPW1206249RBEEA" 1206 3458.58,1805.02 r90 top value=249 (schematic designator R4)
R5 "RT0603DRE0749R9L" 0603 2632.33,1366.22 r0 bottom value=49.9
R6 "CRCW06030000Z0EA" 0603 2648.35,483.47 r0 bottom value=0
R7 "CRCW06038K20JNEA" 0603 2927.75,366.91 r0 bottom value=8.2k
R8 "RC0603FR-07330KL" 0603 2648.35,425.9 r0 top value=330k
R9 "RT0603DRE0749R9L" 0603 2823.4,1125.68 r90 bottom value=49.9
R10 "CRCW060310K0FKEA" 0603S 2252.45,1228.47 r0 top value=10.0k
R11 "RC0603FR-07220KL" 0603 2648.35,483.47 r180 top value=220k
R12 "RT0603DRE0749R9L" 0603S 2429.63,1095.82 r270 top value=49.9
R13 "RC0603FR-074K7L" 0603S 1989.76,712.83 r270 top value=4.70k
R14 "RC0603FR-074K7L" 0603S 1982.73,1178.31 r90 top value=4.70k
R15 "CRCW06030000Z0EA" 0603S 1818.27,1178.31 r90 top value=0
R16 "RC0603JR-0747KL" 0603 2263.93,423.65 r0 top value=47k
R17 "RT0603DRE0749R9L" 0603S 1872.8,1178.31 r90 top value=49.9
R18 "RT0603DRE0749R9L" 0603S 1926.6,1178.31 r90 top value=49.9
R19 "RT0603DRE0749R9L" 0603 2264.42,358.53 r180 top value=49.9
R20 "RT0603DRE0749R9L" 0603S 1926.98,712.83 r90 top value=49.9
R21 "RT0603DRE0749R9L" 0603S 2263.93,480.66 r180 top value=49.9
R22 "RT0603DRE0749R9L" 0603S 2263.93,547.11 r180 top value=49.9
R23 "CRCW06030000Z0EA" 0603S 2170.88,547.11 r270 top value=0
R24 "ERA-3AEB104V" 0603 2263.93,694.17 r180 top value=100k
R25 "RC0603JR-0747KL" 0603 2563.63,718.78 r270 top value=47k
R26 "CRCW06030000Z0EA" 0603 2766.66,1125.68 r90 bottom value=0
R27 "RC0603FR-074K7L" 0603 2632.33,1308.5 r180 bottom value=4.70k
R28 "RC0603FR-074K7L" 0603 2632.33,1250.85 r180 bottom value=4.70k
R29 "RT0603DRE0749R9L" 0603 2936.95,1125.68 r270 bottom value=49.9
R30 "RT0603DRE0749R9L" 0603 2879.9,1125.68 r270 bottom value=49.9
R31 "RC0603FR-074K7L" 0603 1907.36,354.58 r90 bottom value=4.70k
R32 "RC0603FR-074K7L" 0603 2007.75,354.58 r90 bottom value=4.70k
R33 "RG1608P-124-B-T5" 0603 1690.76,1368.05 r0 bottom value=120k
R34 "CRCW04023K30JNED" 0402 2264.75,602.66 r180 top value=3.3k
R35 "ERJ-L03KF47MV" 0603 1900.9,1552.21 r180 bottom value=0.047
R36 "CHV2010-FX-3304ELF" FP-CHV2010-FX-3304ELF_2010-MFG 3760,630 r0 bottom
R37 "CHV2010-FX-3304ELF" FP-CHV2010-FX-3304ELF_2010-MFG 3762.8,1825.12 r0 bottom
R39 "CHV2010-FX-3304ELF" FP-CHV2010-FX-3304ELF_2010-MFG 490.8,174.41 r270 bottom
R40 "CHV2010-FX-3304ELF" FP-CHV2010-FX-3304ELF_2010-MFG 180.09,1825.12 r180 bottom
R41 "CRCW04028K20JNED" 0402 1522.71,1119.49 r90 top value=8.2k
R42 "RG2012P-101-B-T5" 0805 722.59,1387.79 r0 top value=100
R43 "RG2012P-101-B-T5" 0805 532.1,661.85 r180 top value=100
R46 "CRCW040268K0JNED" 0402 860.02,296.66 r0 top value=68k
R47 "RC0603FR-07536KL" 0603S 889.24,387.56 r270 top value=536k
R48 "RC0603FR-07174KL" 0603 699.21,531.08 r0 top value=174k
R50 "RC0603FR-07100KL" 0603S 828.26,387.56 r90 top value=100k
R51 "RC0603FR-07130KL" 0603 670.22,198.74 r180 top value=130k
R52 "RC0603FR-0712K1L" 0603S 733.92,255.9 r180 top value=12.1k
R54 "CRCW04023K30JNED" 0402 1519.93,435.56 r270 top value=3.3k
R55 "CRCW04023K30JNED" 0402 1521.22,1385.75 r270 top value=3.3k
R56 "CRCW060310K0FKEA" 0603S 2489.86,1095.82 r90 top value=10.0k
T1 "750317605" FP-750317605_SMT_XFRMR_9MM5_9MM78-MFG 597.24,927.55 r270 top
TP1 "GND" Keystone5001 3107.64,1280.31 r90 top
TP2 "GND_0V" Keystone5001 3107.64,680.47 r90 top
TP3 "PA18" TP_SM_1MM 2375.41,404.95 r270 top
TP4 "DRDY" TP_SM_1MM 2222.62,1107.22 r0 top
TP5 "SW" Testpoint_Keystone_Miniature 880.44,760.88 r270 top
U1_1 "TVS3301DRBR" DRB0008A 675.61,2148.32 r0 bottom (schematic designator U1)
U1_2 "TVS3301DRBR" DRB0008A 1076.23,2148.32 r0 bottom (schematic designator U1)
U1_3 "TVS3301DRBR" DRB0008A 1476.09,2148.32 r0 bottom (schematic designator U1)
U1_4 "TVS3301DRBR" DRB0008A 1875.95,2148.32 r0 bottom (schematic designator U1)
U1_5 "TVS3301DRBR" DRB0008A 2275.82,2148.32 r0 bottom (schematic designator U1)
U1_6 "TVS3301DRBR" DRB0008A 2675.68,2148.32 r0 bottom (schematic designator U1)
U1_7 "TVS3301DRBR" DRB0008A 3075.54,2148.32 r0 bottom (schematic designator U1)
U1_8 "TVS3301DRBR" DRB0008A 3475.4,2148.32 r0 bottom (schematic designator U1)
U2_1 "TVS3301DRBR" DRB0008A 464.53,2148.32 r180 bottom (schematic designator U2)
U2_2 "TVS3301DRBR" DRB0008A 865.15,2148.32 r180 bottom (schematic designator U2)
U2_3 "TVS3301DRBR" DRB0008A 1265.01,2148.32 r180 bottom (schematic designator U2)
U2_4 "TVS3301DRBR" DRB0008A 1664.87,2148.32 r180 bottom (schematic designator U2)
U2_5 "TVS3301DRBR" DRB0008A 2064.73,2148.32 r180 bottom (schematic designator U2)
U2_6 "TVS3301DRBR" DRB0008A 2464.59,2148.32 r180 bottom (schematic designator U2)
U2_7 "TVS3301DRBR" DRB0008A 2864.45,2148.32 r180 bottom (schematic designator U2)
U2_8 "TVS3301DRBR" DRB0008A 3264.32,2148.32 r180 bottom (schematic designator U2)
U3 "ADS125H18IRHBR" RHB0036A-MFG 2487.64,1291.03 r270 top
U4 "MSPM0G1507SRGE" RGE0024H-MFG 2436.31,526.78 r270 top
U5 "ISO6441DBQR" DBQ0016A-MFG 1896.46,927.13 r90 top
U6 "TXE8116RGER" RGE0024F-MFG 2813.21,1325.59 r180 bottom
U7 "REF6025IDGKR" DGK0008A_N 1900.9,1321.4 r0 bottom
U8 "LM5180NGUR" NGU0008C 682.27,388.27 r270 top
U9 "TPS7A2050PDBVR" DBV0005A-MFG 1417.01,1091.94 r90 top
U10 "TLV709A33DBVR" DBV0005A-MFG 1414.24,408 r90 top
U11 "TLV709A33DBVR" DBV0005A-MFG 1417.01,1347.73 r90 top
U12 "UCC33420" RAQ0012B-MFG 1132.58,927.55 r90 top
ZZ1 "This Assembly Note is for PCB labels only" AssemblyNoteLabel -260,3032.49 r0 top
ZZ2 "These assemblies are ESD sensitive, ESD precautions shall be observed." AssemblyNote -260,2923.6 r0 top
ZZ3 "These assemblies must be clean and free from flux and all contaminants. Use of no clean flux is not acceptable." AssemblyNote -260,2835.05 r0 top
ZZ4 "These assemblies must comply with workmanship standards IPC-A-610 Class 2, unless otherwise specified." AssemblyNote -260,2746.49 r0 top

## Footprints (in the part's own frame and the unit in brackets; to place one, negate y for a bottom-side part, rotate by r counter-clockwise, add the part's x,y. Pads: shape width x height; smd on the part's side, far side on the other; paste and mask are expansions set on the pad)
0402 [mm] "0402 from SM-752 data"
  rect 0.8x0.6 smd: 1(-0.6,0) 2(0.6,0)
  silkscreen extent -1.22,-0.52 1.22,0.52, body extent -0.55,-0.3 0.55,0.3, height 0.6
0603 [mm] "0603 from SM-752 data"
  rect 1x0.95 smd: 1(-0.8,0) 2(0.8,0)
  silkscreen extent -1.52,-0.69 1.52,0.69, body extent -0.87,-0.47 0.87,0.47, height 1
0603S [mil]
  rect 20x35 smd: 1(-30,0) 2(30,0)
  body extent -34,-19 34,19, height 39
0805 [mm] "0805 from SM-752 data"
  rect 1.3x1.5 smd: 1(-0.85,0) 2(0.85,0)
  silkscreen extent -1.72,-0.97 1.72,0.97, body extent -1.1,-0.72 1.1,0.72, height 1.45
0805_HV [mil] "0805 with 30mil clearance between pads"
  rect 50x63 smd: 1(-40,0) 2(40,0)
  silkscreen extent -74,-40 74,40, body extent -43,-29 43,29, height 57
1206 [mm] "1206 from SM-752 data"
  rect 1.3x1.85 smd: 1(-1.45,0) 2(1.45,0)
  silkscreen extent -2.4,-1.21 2.4,1.21, body extent -1.7,-0.9 1.7,0.9, height 1.35
1206_190 [mm] "1206_190"
  rect 1.1x1.6 smd: 1(-1.7,0) 2(1.7,0)
  silkscreen extent -0.9,-1 0.9,1, body extent -1.75,-0.95 1.75,0.95, height 1.9
AssemblyNote [mil] "Assembly Note"
AssemblyNoteLabel [mil] "Assembly Note for PCB Labels"
CE_Mark_5mm [mil] "Minimum text height for CE Mark"
  silkscreen extent -138,-98 138,98
DBQ0016A-MFG [mm] "Recommended Land Pattern"
  rrect24% 1.6x0.41 smd paste+0 mask+0: 1(-2.7,2.222) 2(-2.7,1.587) 3(-2.7,0.952) 4(-2.7,0.317) 5(-2.7,-0.318) 6(-2.7,-0.953) 7(-2.7,-1.588) 8(-2.7,-2.222) 9(2.7,-2.222) 10(2.7,-1.587) 11(2.7,-0.952) 12(2.7,-0.317) 13(2.7,0.318) 14(2.7,0.953) 15(2.7,1.588) 16(2.7,2.222)
  silkscreen extent -4.17,-2.5 1.5,2.5, body extent -3,-2.45 3,2.45, height 1.75
DBV0005A-MFG [mm]
  rrect17% 1.1x0.6 smd paste+0 mask+0: 1(-1.3,0.95) 2(-1.3,0) 3(-1.3,-0.95) 4(1.3,-0.95) 5(1.3,0.95)
  silkscreen extent -2.57,-1.53 0.87,1.53, body extent -1.95,-1.78 1.95,1.78, height 0.25
DBZ0003A-MFG [mm] "Recommended Land Pattern"
  rrect17% 1.3x0.6 smd paste+0 mask+0: 1(-1.05,0.95) 2(-1.05,-0.95) 3(1.05,0)
  silkscreen extent -0.7,-1.52 0.7,1.52, body extent -1.18,-1.46 1.18,1.46, height 1.12
DGK0008A_N [mm] "TSOP, 8-Leads, Body 3x3mm, Pitch 0.65mm, IPC Medium Density"
  oval 1.35x0.45 smd: 1(-2.225,0.975) 2(-2.225,0.325) 3(-2.225,-0.325) 4(-2.225,-0.975) 5(2.225,-0.975) 6(2.225,-0.325) 7(2.225,0.325) 8(2.225,0.975)
  silkscreen extent -2.75,-1.55 0.95,1.55, body extent -2.45,-1.5 2.45,1.5, height 0.96
DPY0002A#1 [mm] "X1SON-2"
  rrect57% 0.35x0.6 smd paste-0.5 mask-0.05: 1(-0.325,0) 2(0.325,0)
  rrect33% 0.3x0.5 on Top Paste: 1S(-0.35,0) 2S(0.35,0)
  silkscreen extent -0.85,-0.02 -0.8,0.02, body extent -0.5,-0.3 0.5,0.3, height 0.45
DPY0002A#2 [mm] "X1SON-2"
  rrect57% 0.35x0.6 smd paste-0.5 mask-0.05: 1(-0.325,0) 2(0.325,0)
  rrect33% 0.3x0.5 on Bottom Paste: 1S(-0.35,0) 2S(0.35,0)
  silkscreen extent -0.85,-0.02 -0.8,0.02, body extent -0.5,-0.3 0.5,0.3, height 0.45
DRB0008A [mm] "VSON-8"
  rrect32% 0.6x0.31 smd: 1(-1.4,0.975) 2(-1.4,0.325) 3(-1.4,-0.325) 4(-1.4,-0.975) 5(1.4,-0.975) 6(1.4,-0.325) 7(1.4,0.325) 8(1.4,0.975)
  rrect7% 1.5x1.75 smd paste-0.75: 9(0,0)
  Top Layer region: -0.7,-0.875 -0.49,-0.875 -0.471,-0.879 -0.455,-0.89 -0.444,-0.906 -0.44,-0.925 -0.44,-0.925 -0.44,-1.65 -0.436,-1.669 -0.425,-1.685 -0.409,-1.696 -0.39,-1.7 -0.39,-1.7 -0.26,-1.7 -0.241,-1.696 -0.225,-1.685 -0.214,-1.669 -0.21,-1.65 -0.21,-1.65 -0.21,-0.925 -0.206,-0.906 -0.195,-0.89 -0.179,-0.879 -0.16,-0.875 -0.16,-0.875 0.16,-0.875 0.179,-0.879 0.195,-0.89 0.206,-0.906 0.21,-0.925 0.21,-0.925 0.21,-1.65 0.21,-1.65 0.214,-1.669 0.225,-1.685 0.241,-1.696 0.26,-1.7 0.26,-1.7 0.39,-1.7 0.409,-1.696 0.425,-1.685 0.436,-1.669 0.44,-1.65 0.44,-1.65 0.44,-0.925 0.444,-0.906 0.455,-0.89 0.471,-0.879 0.49,-0.875 0.49,-0.875 0.7,-0.875 0.719,-0.871 0.735,-0.86 0.746,-0.844 0.75,-0.825 0.75,-0.825 0.75,0.825 0.746,0.844 0.735,0.86 0.719,0.871 0.7,0.875 0.7,0.875 0.49,0.875 0.471,0.879 0.455,0.89 0.444,0.906 0.44,0.925 0.44,0.925 0.44,1.65 0.436,1.669 0.425,1.685 0.409,1.696 0.39,1.7 0.39,1.7 0.26,1.7 0.241,1.696 0.225,1.685 0.214,1.669 0.21,1.65 0.21,1.65 0.21,1.65 0.21,0.925 0.206,0.906 0.195,0.89 0.179,0.879 0.16,0.875 0.16,0.875 -0.16,0.875 -0.179,0.879 -0.195,0.89 -0.206,0.906 -0.21,0.925 -0.21,0.925 -0.21,1.65 -0.214,1.669 -0.225,1.685 -0.241,1.696 -0.26,1.7 -0.26,1.7 -0.39,1.7 -0.409,1.696 -0.425,1.685 -0.436,1.669 -0.44,1.65 -0.44,1.65 -0.44,0.925 -0.444,0.906 -0.455,0.89 -0.471,0.879 -0.49,0.875 -0.49,0.875 -0.7,0.875 -0.719,0.871 -0.735,0.86 -0.746,0.844 -0.75,0.825 -0.75,0.825 -0.75,-0.825 -0.746,-0.844 -0.735,-0.86 -0.719,-0.871 -0.7,-0.875
  silkscreen extent -1.73,-1.73 1.73,1.73, body extent -1.5,-1.5 1.5,1.5, height 0.77
FCC_disclaimer [mil]
Fiducial10-20 [mm]
  round 1 smd mask+0.5: 1(0,0)
  Top Layer keep-out circle w1.178: c0,0 r0.5
FP-750317605_SMT_XFRMR_9MM5_9MM78-MFG [mm]
  rrect9% 1.91x1.17 smd paste+0 mask+0: 1(4.065,3.735) 2(4.065,1.245) 3(4.065,-1.245) 4(4.065,-3.735) 5(-4.065,-3.735) 6(-4.065,-1.245) 7(-4.065,1.245) 8(-4.065,3.735)
  silkscreen extent -4.75,-4.89 5.7,4.89, body extent -5.12,-4.99 5.12,4.99, height 0.25
FP-629105150521_CONN_USB_8MM0_6MM6-MFG [mm]
  rect 0.45x1.3 smd: 1(-1.3,0) 2(-0.65,0) 3(0,0) 4(0.65,0) 5(1.3,0)
  oval 1.4x2 hole 0.85 slot 1.4 at 90 deg: Z1(-3.725,0) Z2(3.725,0)
  oval 1.15x1.8 hole 0.55 slot 1.2 at 90 deg: Z3(3.875,-3.8) Z4(-3.875,-3.8)
  round 0.8 hole 0.8 unplated: ""(-2.5,-1.1) ""(2.5,-1.1)
  silkscreen extent -4,-6.2 4,0.9, body extent -4,-6.25 4,0.35, height 2.67
FP-691103110002_CONN_TERM_POS2-MFG [mm]
  rrect5% 1.85x1.85 hole 1.2 paste-1000 mask+0: 1(-1.75,0.1)
  round 1.85 hole 1.2 paste-1000 mask+0: 2(1.75,0.1)
  silkscreen extent -4.38,-4.25 4.38,3.65, body extent -4.47,-3.75 4.47,3.75, height 0.25
FP-885012106031_0603-MFG [mm]
  rrect13% 0.8x0.8 smd paste+0 mask+0: 1(-0.75,0) 2(0.75,0)
  silkscreen extent -0.9,-0.77 0.9,0.77, body extent -1.25,-0.6 1.25,0.6, height 0.25
FP-885012208094_1206-MFG [mm]
  rrect11% 0.9x1.6 smd paste+0 mask+0: 1(-1.55,0) 2(1.55,0)
  silkscreen extent -0.72,-0.95 0.72,0.95, body extent -2.1,-1.05 2.1,1.05, height 0.25
FP-885012209048_1210-MFG [mm]
  rrect11% 0.9x2.5 smd paste+0 mask+0: 1(-1.55,0) 2(1.55,0)
  silkscreen extent -0.72,-1.35 0.72,1.35, body extent -2.1,-1.45 2.1,1.45, height 0.25
FP-885012209074_1210-MFG [mm]
  rrect11% 0.9x2.5 smd paste+0 mask+0: 1(-1.55,0) 2(1.55,0)
  silkscreen extent -0.72,-1.35 0.72,1.35, body extent -1.6,-1.25 1.6,1.25, height 2.7
FP-AQY232G3HS_SOP4-MFG [mm] "Recommended Land Pattern"
  rrect13% 1.2x0.8 smd paste+0 mask+0: 1(-3,1.27) 2(-3,-1.27) 3(3,-1.27) 4(3,1.27)
  silkscreen extent -4.22,-2.25 2,2.25, body extent -3.4,-2.15 3.4,2.15, height 2.4
FP-CHV2010-FX-3304ELF_2010-MFG [mm]
  rrect7% 1.5x3 smd paste+0 mask+0: 1(-2.65,0) 2(2.65,0)
  silkscreen extent -1.53,-1.35 1.53,1.35, body extent -2.5,-1.25 2.5,1.25, height 0.7
FP-nanoASMDCH020F-2_1206-MFG [mm] "Recommended Land Pattern"
  rrect10% 1x1.6 smd paste+0 mask+0: 1(-1.5,0) 2(1.5,0)
  silkscreen extent -0.63,-0.9 0.63,0.9, body extent -1.6,-0.79 1.6,0.79, height 0.85
FP-RBS1LAM40ATR_SOD128-MFG [mm]
  rrect7% 1.4x2 smd paste+0 mask+0: 1(-2.2,0) 2(2.2,0)
  silkscreen extent -3.56,-1.35 1.91,1.35, body extent -2.35,-1.25 2.35,1.25, height 1.05
Harwin_M22-2510505 [mm] "Header, 2mm, 5x1, TH"
  rect 1.3x1.3 hole 0.8: 1(-4,0)
  round 1.3 hole 0.8: 2(-2,0) 3(0,0) 4(2,0) 5(4,0)
  silkscreen extent -5,-1 5,1.3, body extent -5,-1 5,1, height 5
Keystone5001 [mil] "For Keystone 500x miniature loop terminals"
  round 80 hole 40: 1(0,0)
  silkscreen extent -52,-52 52,52, body extent -49,-49 49,49, height 182
Keystone_1902C [mil] "Hex Standoff, 4-40 threaded, nylon"
  round 1 on Mech4: 0(0,0)
  body extent -145,-126 146,126, height 501
Label_650x200 [mil] "Thermal Transfer Label"
  round 1 on Mech13: 0(0,0)
  silkscreen extent -325,-100 325,100, body extent -325,-100 325,100, height 1
NGU0008C [mm] "SON, 8-Leads, Body 4x4mm, Pitch 0.8mm"
  rrect33% 0.6x0.3 smd: 1(-1.9,1.2) 2(-1.9,0.4) 3(-1.9,-0.4) 4(-1.9,-1.2) 5(1.9,-1.2) 6(1.9,-0.4) 7(1.9,0.4) 8(1.9,1.2)
  rrect8% 1.75x1.31 on Top Paste: 9(0,0.755) 9(0,-0.755)
  rrect5% 1.98x3 smd paste-1.5: 9(0,0)
  silkscreen extent -2.15,-2.15 2.15,2.15, body extent -2,-2 2,2, height 0.77
"NY PMS 440 0025 PH" [mm] "4-40 nylon screw and mounting hole"
  round 8 hole 3.2: 1(0,0)
  body extent -3.3,-3.3 3.3,3.3, height 2.69
RAQ0012B-MFG [mm]
  rrect33% 0.6x0.3 smd paste+0 mask+0: 1(-2.4,1.625) 2(-2.4,0.975) 3(-2.4,0.325) 4(-2.4,-0.325) 5(-2.4,-0.975) 6(-2.4,-1.625) 7(2.4,-1.625) 8(2.4,-0.975) 9(2.4,-0.325) 10(2.4,0.325) 11(2.4,0.975) 12(2.4,1.625)
  Top Layer region: 2.65,-0.475 2.675,-0.468 2.693,-0.45 2.7,-0.425 2.7,-0.425 2.7,-0.225 2.696,-0.206 2.685,-0.19 2.669,-0.179 2.65,-0.175 2.65,-0.175 2.45,-0.175 2.431,-0.171 2.415,-0.16 2.404,-0.144 2.4,-0.125 2.4,-0.125 2.4,0.125 2.404,0.144 2.415,0.16 2.431,0.171 2.45,0.175 2.45,0.175 2.65,0.175 2.675,0.182 2.693,0.2 2.7,0.225 2.7,0.225 2.7,0.425 2.696,0.444 2.685,0.46 2.669,0.471 2.65,0.475 2.65,0.475 2.45,0.475 2.431,0.479 2.415,0.49 2.404,0.506 2.4,0.525 2.4,0.525 2.4,0.775 2.404,0.794 2.415,0.81 2.431,0.821 2.45,0.825 2.45,0.825 2.65,0.825 2.669,0.829 2.685,0.84 2.696,0.856 2.7,0.875 2.7,0.875 2.7,1.075 2.693,1.1 2.675,1.118 2.65,1.125 2.65,1.125 2.15,1.125 2.131,1.121 2.115,1.11 2.104,1.094 2.1,1.075 2.1,1.075 2.1,-0.425 2.104,-0.444 2.115,-0.46 2.131,-0.471 2.15,-0.475 2.15,-0.475
  Top Layer region: -2.65,-1.125 -2.675,-1.118 -2.693,-1.1 -2.7,-1.075 -2.7,-1.075 -2.7,-0.875 -2.696,-0.856 -2.685,-0.84 -2.669,-0.829 -2.65,-0.825 -2.65,-0.825 -2.45,-0.825 -2.431,-0.821 -2.415,-0.81 -2.404,-0.794 -2.4,-0.775 -2.4,-0.775 -2.4,-0.525 -2.404,-0.506 -2.415,-0.49 -2.431,-0.479 -2.45,-0.475 -2.45,-0.475 -2.65,-0.475 -2.675,-0.468 -2.693,-0.45 -2.7,-0.425 -2.7,-0.425 -2.7,-0.225 -2.696,-0.206 -2.685,-0.19 -2.669,-0.179 -2.65,-0.175 -2.65,-0.175 -2.45,-0.175 -2.431,-0.171 -2.415,-0.16 -2.404,-0.144 -2.4,-0.125 -2.4,-0.125 -2.4,0.125 -2.404,0.144 -2.415,0.16 -2.431,0.171 -2.45,0.175 -2.45,0.175 -2.65,0.175 -2.675,0.182 -2.693,0.2 -2.7,0.225 -2.7,0.225 -2.7,0.425 -2.693,0.45 -2.675,0.468 -2.65,0.475 -2.65,0.475 -2.15,0.475 -2.131,0.471 -2.115,0.46 -2.104,0.444 -2.1,0.425 -2.1,0.425 -2.1,-1.075 -2.104,-1.094 -2.115,-1.11 -2.131,-1.121 -2.15,-1.125 -2.15,-1.125
  silkscreen extent -3.37,-2.05 1.73,2.55, body extent -2.8,-2.15 2.8,2.15, height 0.25
RGE0024F-MFG [mm]
  rrect42% 0.6x0.24 smd paste+0 mask+0: 1(-1.9,1.25) 2(-1.9,0.75) 3(-1.9,0.25) 4(-1.9,-0.25) 5(-1.9,-0.75) 6(-1.9,-1.25) 13(1.9,-1.25) 14(1.9,-0.75) 15(1.9,-0.25) 16(1.9,0.25) 17(1.9,0.75) 18(1.9,1.25)
  rrect42% 0.24x0.6 smd paste+0 mask+0: 7(-1.25,-1.9) 8(-0.75,-1.9) 9(-0.25,-1.9) 10(0.25,-1.9) 11(0.75,-1.9) 12(1.25,-1.9) 19(1.25,1.9) 20(0.75,1.9) 21(0.25,1.9) 22(-0.25,1.9) 23(-0.75,1.9) 24(-1.25,1.9)
  rrect4% 2.8x2.8 smd paste-1000 mask+0: 25(0,0)
  silkscreen extent -2.88,-2.05 2.05,2.05, body extent -2,-2 2,2, height 1
RGE0024H-MFG [mm]
  rrect42% 0.58x0.24 smd paste+0 mask+0: 1(-1.913,1.25) 2(-1.913,0.75) 3(-1.913,0.25) 4(-1.913,-0.25) 5(-1.913,-0.75) 6(-1.913,-1.25) 13(1.913,-1.25) 14(1.913,-0.75) 15(1.913,-0.25) 16(1.913,0.25) 17(1.913,0.75) 18(1.913,1.25)
  rrect42% 0.24x0.58 smd paste+0 mask+0: 7(-1.25,-1.913) 8(-0.75,-1.913) 9(-0.25,-1.913) 10(0.25,-1.913) 11(0.75,-1.913) 12(1.25,-1.913) 19(1.25,1.913) 20(0.75,1.913) 21(0.25,1.913) 22(-0.25,1.913) 23(-0.75,1.913) 24(-1.25,1.913)
  rrect4% 2.7x2.7 smd paste-1000 mask+0: 25(0,0)
  silkscreen extent -2.95,-2.05 2.05,2.05, body extent -2.3,-2.3 2.3,2.3, height 0.25
RHB0036A-MFG [mm]
  rrect40% 0.6x0.25 smd paste+0 mask+0: 1(-2.4,1.75) 2(-2.4,1.25) 3(-2.4,0.75) 4(-2.4,0.25) 5(-2.4,-0.25) 6(-2.4,-0.75) 7(-2.4,-1.25) 8(-2.4,-1.75) 19(2.4,-1.75) 20(2.4,-1.25) 21(2.4,-0.75) 22(2.4,-0.25) 23(2.4,0.25) 24(2.4,0.75) 25(2.4,1.25) 26(2.4,1.75)
  round 0.27 smd paste+0 mask+0: 9(-2.25,-2.25) 18(2.25,-2.25) 27(2.25,2.25) 36(-2.25,2.25)
  rrect40% 0.25x0.6 smd paste+0 mask+0: 10(-1.75,-2.4) 11(-1.25,-2.4) 12(-0.75,-2.4) 13(-0.25,-2.4) 14(0.25,-2.4) 15(0.75,-2.4) 16(1.25,-2.4) 17(1.75,-2.4) 28(1.75,2.4) 29(1.25,2.4) 30(0.75,2.4) 31(0.25,2.4) 32(-0.25,2.4) 33(-0.75,2.4) 34(-1.25,2.4) 35(-1.75,2.4)
  rrect3% 3.8x3.8 smd paste-1000 mask+0: 37(0,0)
  Top Layer region: -2.375,-2.65 -2.371,-2.669 -2.36,-2.685 -2.344,-2.696 -2.325,-2.7 -2.325,-2.7 -2.15,-2.7 -2.125,-2.693 -2.107,-2.675 -2.1,-2.65 -2.1,-2.65 -2.1,-2.15 -2.104,-2.131 -2.115,-2.115 -2.131,-2.104 -2.15,-2.1 -2.15,-2.1 -2.65,-2.1 -2.669,-2.104 -2.685,-2.115 -2.696,-2.131 -2.7,-2.15 -2.7,-2.15 -2.7,-2.325 -2.696,-2.344 -2.685,-2.36 -2.669,-2.371 -2.65,-2.375 -2.65,-2.375 -2.495,-2.375 -2.449,-2.384 -2.41,-2.41 -2.384,-2.449 -2.375,-2.495 -2.375,-2.495
  Top Layer region: 2.375,-2.65 2.371,-2.669 2.36,-2.685 2.344,-2.696 2.325,-2.7 2.325,-2.7 2.15,-2.7 2.125,-2.693 2.107,-2.675 2.1,-2.65 2.1,-2.65 2.1,-2.15 2.104,-2.131 2.115,-2.115 2.131,-2.104 2.15,-2.1 2.15,-2.1 2.65,-2.1 2.669,-2.104 2.685,-2.115 2.696,-2.131 2.7,-2.15 2.7,-2.15 2.7,-2.325 2.696,-2.344 2.685,-2.36 2.669,-2.371 2.65,-2.375 2.65,-2.375 2.495,-2.375 2.449,-2.384 2.41,-2.41 2.384,-2.449 2.375,-2.495 2.375,-2.495
  Top Layer region: 2.375,2.65 2.371,2.669 2.36,2.685 2.344,2.696 2.325,2.7 2.325,2.7 2.15,2.7 2.125,2.693 2.107,2.675 2.1,2.65 2.1,2.65 2.1,2.15 2.104,2.131 2.115,2.115 2.131,2.104 2.15,2.1 2.15,2.1 2.65,2.1 2.669,2.104 2.685,2.115 2.696,2.131 2.7,2.15 2.7,2.15 2.7,2.325 2.696,2.344 2.685,2.36 2.669,2.371 2.65,2.375 2.65,2.375 2.495,2.375 2.449,2.384 2.41,2.41 2.384,2.449 2.375,2.495 2.375,2.495
  Top Layer region: -2.375,2.65 -2.368,2.675 -2.35,2.693 -2.325,2.7 -2.325,2.7 -2.15,2.7 -2.125,2.693 -2.107,2.675 -2.1,2.65 -2.1,2.65 -2.1,2.15 -2.104,2.131 -2.115,2.115 -2.131,2.104 -2.15,2.1 -2.15,2.1 -2.65,2.1 -2.669,2.104 -2.685,2.115 -2.696,2.131 -2.7,2.15 -2.7,2.15 -2.7,2.325 -2.693,2.35 -2.675,2.368 -2.65,2.375 -2.65,2.375 -2.495,2.375 -2.449,2.384 -2.41,2.41 -2.384,2.449 -2.375,2.495 -2.375,2.495
  silkscreen extent -3.37,-2.93 2.93,2.93, body extent -2.8,-2.8 2.8,2.8, height 0.25
SMA [mm] "Molded Diode, 2-Leads, Body 4.3x2.6mm, IPC Medium Density, based on OnSemi component dimensions and land pattern"
  rect 2x2 smd: 1(-2,0) 2(2,0)
  silkscreen extent -3.66,-1.57 2.79,1.57, body extent -2.6,-1.3 2.6,1.3, height 2.42
SMB [mil] "Molded Diode, 2-Leads, Body 5.4x3.6mm, IPC Medium Density, based on OnSemi component dimensions"
  rect 85x107.99 smd: 1(-87.01,0) 2(87.01,0)
  silkscreen extent -155,-82 125,82, body extent -106,-71 106,71, height 91
SOD-323 [mm] "NXP recommended land pattern"
  rect 0.6x0.6 smd paste-0.05: 1(-1.1,0) 2(1.1,0)
  silkscreen extent -2.06,-0.86 1.53,0.86, body extent -1.3,-0.67 1.3,0.68, height 1.1
SOT-23 [mm] "SOT23, 3-Leads, Body 2.9x1.3mm, Pitch 0.95mm, Lead Span 2.5mm, IPC Medium Density"
  rrect50% 1x0.6 smd: 1(-1.2,0.95) 2(-1.2,-0.95) 3(1.2,0)
  silkscreen extent -1.62,-1.5 0.7,1.5, body extent -1.16,-1.45 1.21,1.45, height 1
Testpoint_Keystone_Miniature [mil] "Miniature SMT test point"
  rect 135x70 smd: 1(0,0)
  silkscreen extent -78,-46 78,45, body extent -52,-20 52,20, height 61
TI_Stacked_Overlay_Small [mil]
  silkscreen extent -418,-98 418,98
TP_SM_1MM [mm] "1mm Test Point, SMT"
  round 1 smd paste-0.5: 1(0,0)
